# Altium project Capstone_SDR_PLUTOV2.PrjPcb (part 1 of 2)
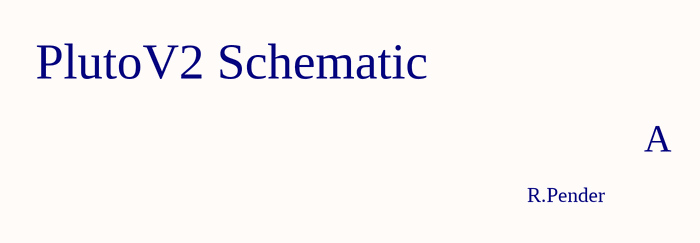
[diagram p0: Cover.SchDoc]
13 sheets, 418 parts. Net scope: global (net labels, ports and power ports of the same name join across sheets).
Sheets:
  Cover.SchDoc
  USB.SchDoc
  DDR3.SchDoc
  ZYNQ JTAG and Decoupling.SchDoc
  ZYNQ 34_35 and QPSI.SchDoc
  AD9363.SchDoc
  RF FRONTEND.SchDoc
  CONNECTORS_SELECTORS.SchDoc
  POWERREG.SchDoc
  POWERMANAGE.SchDoc
  POWERMANAGE2.SchDoc
  TESTPOINTS.SchDoc
  AD9363 OSCILLATORS.SchDoc

## Sheet Cover.SchDoc
size A3; SheetNumber: 1; SheetTotal: 2

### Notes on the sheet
- PlutoV2 Schematic
- A
- R.Pender

## Sheet USB.SchDoc
size A3; SheetNumber: 2; SheetTotal: 13; SPICEModelCacheQEWUXKYK: <root> / <DocumentId>QEWUXKYK</DocumentId> / </root>
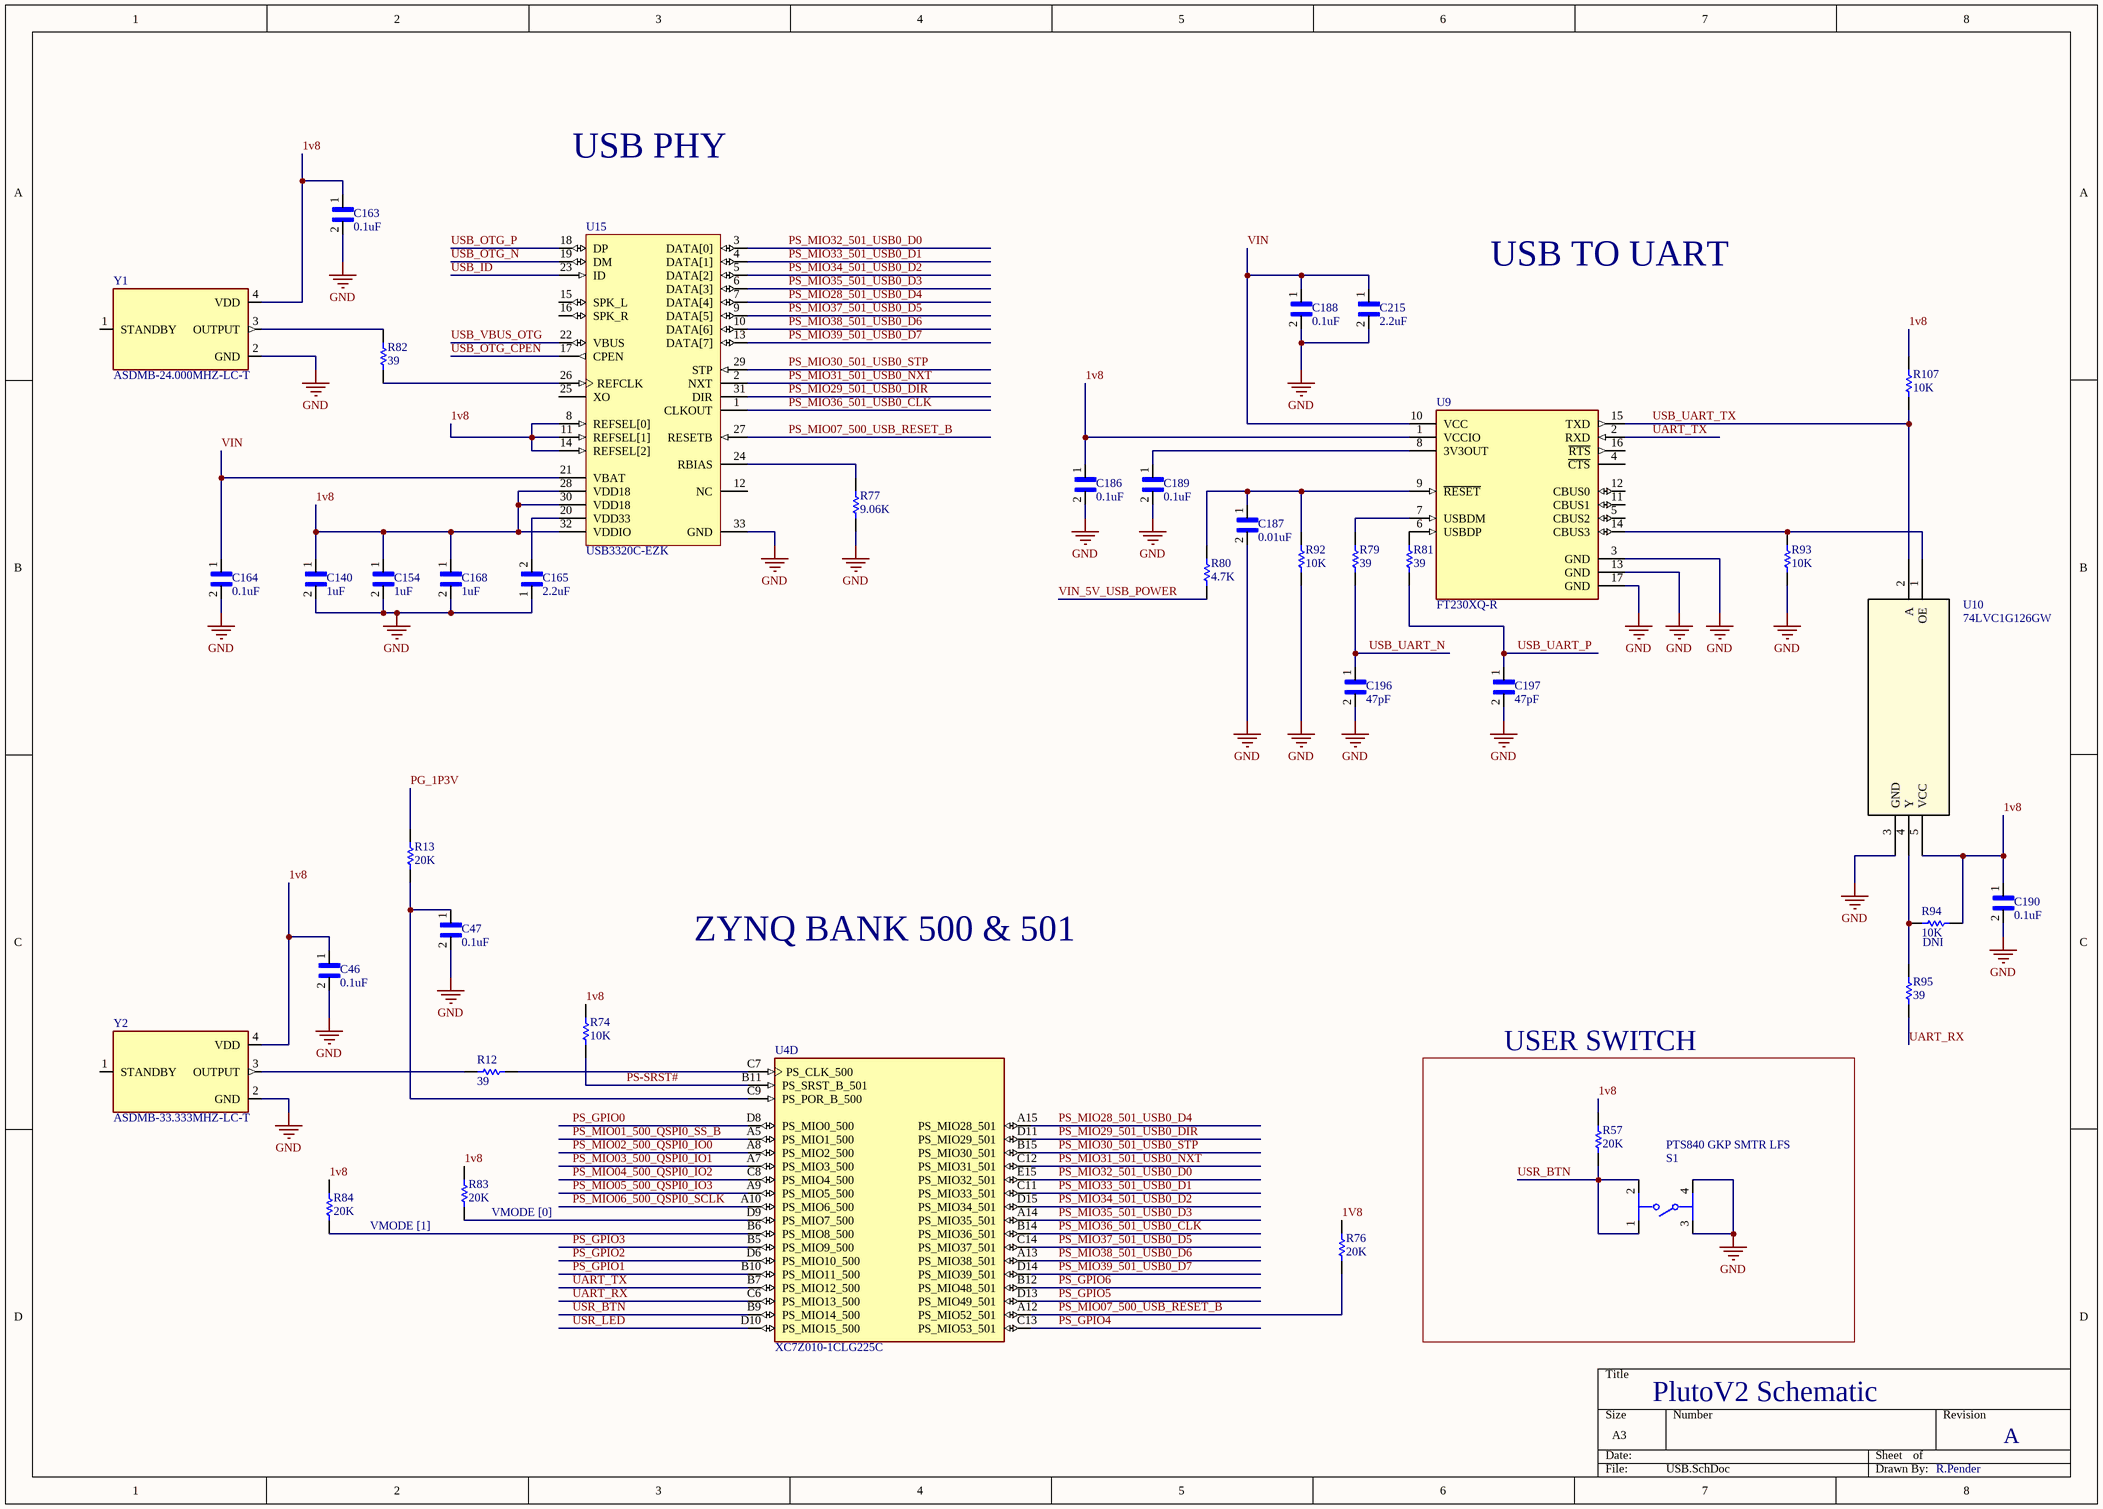
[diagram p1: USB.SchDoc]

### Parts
C46  0.1uF  [CAPC0603X33N]
C47  0.1uF  [CAPC0603X33N]
C140  1uF  [CAPC1005X55N]
C154  1uF  [CAPC1005X55N]
C163  0.1uF  [CAPC0603X33N]
C164  0.1uF  [CAPC0603X33N]
C165  2.2uF  [CAPC1608X100N]
C168  1uF  [CAPC1005X55N]
C186  0.1uF  [CAPC1005X55N]
C187  0.01uF  [CAPC0603X33N]
C188  0.1uF  [CAPC0603X33N]
C189  0.1uF  [CAPC0603X33N]
C190  0.1uF  [CAPC0603X33N]
C196  47pF  [CAPC1005X55N]
C197  47pF  [CAPC1005X55N]
C215  2.2uF  [CAPC1608X100N]
R12  39  [2-0402]
R13  20K  [2-0402]
R57  20K  [2-0402]
R74  10K  [2-0402]
R76  20K  [2-0402]
R77  9.06K  [2-0402]
R79  39  [2-0402]
R80  4.7K  [2-0402]
R81  39  [2-0402]
R82  39  [2-0402]
R83  20K  [2-0402]
R84  20K  [2-0402]
R92  10K  [2-0402]
R93  10K  [2-0402]
R94  10K  [2-0402]
R95  39  [2-0402]
R107  10K  [2-0402]
S1  PTS840 GKP SMTR LFS  [FP-PTS840_GKP_SMTR_LFS-MFG]
U4  XC7Z010-1CLG225C  [BGA225C80P15X15_1300X1300X150]  (part D of 6)
U9  FT230XQ-R  [FP-QFN-16-MFG]
U10  74LVC1G126GW  [SOT353-1_NXP]
U15  USB3320C-EZK  [MCHP-QFN-32-5x5_V2]
Y1  ASDMB-24.000MHZ-LC-T  [XTAL_ASDMB-24.000MHZ-LC-T]
Y2  ASDMB-33.333MHZ-LC-T  [XTAL_ASDMB-24.000MHZ-LC-T]

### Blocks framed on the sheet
USER SWITCH: R57 S1

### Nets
GND: C46.2 C47.2 C140.2 C154.2 C163.2 C164.2 C165.1 C168.2 C186.2 C187.2 C188.2 C189.2 C190.2 C196.2 C197.2 C215.2 R77.1 R92.1 R93.2 S1.3 S1.4 U9.3(GND) U9.13(GND) U9.17(GND) U10.3(GND) U15.33(GND) Y1.2(GND) Y2.2(GND)
1v8: C46.1 C140.1 C154.1 C163.1 C168.1 C186.1 C190.1 R57.1 R74.2 R76.2 R83.1 R84.1 R94.2 R107.1 U9.1(VCCIO) U10.5(VCC) U15.8(REFSEL[0]) U15.11(REFSEL[1]) U15.14(REFSEL[2]) U15.28(VDD18) U15.30(VDD18) U15.32(VDDIO) Y1.4(VDD) Y2.4(VDD)
PG_1P3V: R13.2
PS-SRST#: R74.1 U4.B11(PS_SRST_B_501)
PS_GPIO0: U4.D8(PS_MIO0_500)
PS_GPIO1: U4.B10(PS_MIO11_500)
PS_GPIO2: U4.D6(PS_MIO10_500)
PS_GPIO3: U4.B5(PS_MIO9_500)
PS_GPIO4: U4.C13(PS_MIO53_501)
PS_GPIO5: U4.D13(PS_MIO49_501)
PS_GPIO6: U4.B12(PS_MIO48_501)
PS_MIO01_500_QSPI0_SS_B: U4.A5(PS_MIO1_500)
PS_MIO02_500_QSPI0_IO0: U4.A8(PS_MIO2_500)
PS_MIO03_500_QSPI0_IO1: U4.A7(PS_MIO3_500)
PS_MIO04_500_QSPI0_IO2: U4.C8(PS_MIO4_500)
PS_MIO05_500_QSPI0_IO3: U4.A9(PS_MIO5_500)
PS_MIO06_500_QSPI0_SCLK: U4.A10(PS_MIO6_500)
PS_MIO07_500_USB_RESET_B: R76.1 U4.A12(PS_MIO52_501) U15.27(RESETB)
PS_MIO28_501_USB0_D4: U4.A15(PS_MIO28_501) U15.7(DATA[4])
PS_MIO29_501_USB0_DIR: U4.D11(PS_MIO29_501) U15.31(DIR)
PS_MIO30_501_USB0_STP: U4.B15(PS_MIO30_501) U15.29(STP)
PS_MIO31_501_USB0_NXT: U4.C12(PS_MIO31_501) U15.2(NXT)
PS_MIO32_501_USB0_D0: U4.E15(PS_MIO32_501) U15.3(DATA[0])
PS_MIO33_501_USB0_D1: U4.C11(PS_MIO33_501) U15.4(DATA[1])
PS_MIO34_501_USB0_D2: U4.D15(PS_MIO34_501) U15.5(DATA[2])
PS_MIO35_501_USB0_D3: U4.A14(PS_MIO35_501) U15.6(DATA[3])
PS_MIO36_501_USB0_CLK: U4.B14(PS_MIO36_501) U15.1(CLKOUT)
PS_MIO37_501_USB0_D5: U4.C14(PS_MIO37_501) U15.9(DATA[5])
PS_MIO38_501_USB0_D6: U4.A13(PS_MIO38_501) U15.10(DATA[6])
PS_MIO39_501_USB0_D7: U4.D14(PS_MIO39_501) U15.13(DATA[7])
UART_RX: R95.2 U4.C6(PS_MIO13_500)
UART_TX: U4.B7(PS_MIO12_500) U9.2(RXD)
USB_ID: U15.23(ID)
USB_OTG_CPEN: U15.17(CPEN)
USB_OTG_N: U15.19(DM)
USB_OTG_P: U15.18(DP)
USB_UART_N: C196.1 R79.2
USB_UART_P: C197.1 R81.1
USB_UART_TX: R107.2 U9.15(TXD) U10.2(A)
USB_VBUS_OTG: U15.22(VBUS)
USR_BTN: R57.2 S1.1 S1.2 U4.B9(PS_MIO14_500)
USR_LED: U4.D10(PS_MIO15_500)
VIN: C164.1 C188.1 C215.1 U9.10(VCC) U15.21(VBAT)
VIN_5V_USB_POWER: R80.1
NetC47_1: C47.1 R13.1 U4.C9(PS_POR_B_500)
NetC165_2: C165.2 U15.20(VDD33)
NetC187_1: C187.1 R80.2 R92.2 U9.9(~{RESET})
NetC189_1: C189.1 U9.8(3V3OUT)
NetR12_1: R12.1 Y2.3(OUTPUT)
NetR12_2: R12.2 U4.C7(PS_CLK_500)
NetR77_2: R77.2 U15.24(RBIAS)
NetR79_1: R79.1 U9.7(USBDM)
NetR81_2: R81.2 U9.6(USBDP)
NetR82_1: R82.1 U15.26(REFCLK)
NetR82_2: R82.2 Y1.3(OUTPUT)
NetR83_2: R83.2 U4.D9(PS_MIO7_500)
NetR84_2: R84.2 U4.B6(PS_MIO8_500)
NetR93_1: R93.1 U9.14(CBUS3) U10.1(OE)
NetR94_1: R94.1 R95.1 U10.4(Y)

Not connected (* = marked no-connect by the designer): U9 4(~{CTS}) 5(CBUS2) 11(CBUS1) 12(CBUS0) 16(~{RTS}); U15 12(NC) 15(SPK_L) 16(SPK_R) 25(XO); Y1 1(STANDBY); Y2 1(STANDBY)

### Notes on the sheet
- USB PHY
- USB TO UART
- ZYNQ BANK 500 & 501
- (near R94) DNI
- VMODE [1]
- (near R83) VMODE [0]
- PlutoV2 Schematic
- A
- R.Pender

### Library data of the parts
C46 C47 C163 C164 C188-C190 = GRM033R61C104ME84D: CAP 0.1UF 16VDC X5R 20% SMD 0201 PAPER TAPE
C140 C154 C168 C186 = EMK105BJ105KV-F: 1ÂµF Â± 10% 16V Condensateur cÃ©ramique X5R 0402 _1005 mÃ©trique_; MF: Taiyo Yuden
C165 C215 = GRM188R61H225KE11J: SMD Capacitor X5R(EIA) with Capacitance: 2.2uF Tol. 10%. Rated Voltage: 50Vdc; MF: Murata
C187 = GRM033R71A103KA01D: SMD Capacitor X7R(EIA) with Capacitance: 10000pF Tol. 10%. Rated Voltage: 10Vdc; MF: Murata
C196 C197 = GCM1555C1H470JA16D: 47pF Â±5% 50V Ceramic Capacitor C0G, NP0 0402 (1005 Metric); MF: Murata
R12 R79 R81 R82 R95 = ERJ2GE: Thick Film Chip Resistor, 1 Ohm to 2.2M Ohm Range, 5% Tolerance, 0402 Size, 0.063 W; Note: If flow soldering, adjust pad width of PCB Footprint to 0.7 - 0.8 times the width of the resistor.
R13 R57 R74 R76 R77 R80 R83 R84 R92-R94 R107 = ERJ2RK: Precision Thick Film Chip Resistor, 10 Ohm to 1M Ohm Range, 1% and 0.5% Tolerance, 0402 Size, 0.063 W
S1 = CMP-10040-000012-1: SWITCH TACTILE SPST-NO 0.05A 12V; Manufacturer: C&K Components; Electromechanical Life: 100000Cycles; Contact Current Rating: 50mA; Operating Force: 220gf; Standoff Height: 0mm; Contact Resistance: 500mΩ
U4 = XC7Z010-1CLG225C: Dual ARMÂ® CortexÂ®-A9 MPCoreâ„¢ with CoreSightâ„¢ System On Chip _SOC_ IC ZynqÂ®-7000 Artixâ„¢-7 FPGA, 28K Logic Cells 667MHz 225-CSPBGA _13x13_; MF: Xilinx Inc.
U9 = CMP-0248-00010-3: IC USB SERIAL BASIC UART 16QFN; Number of Channels: 1; Data Rate: 12Mbps; Operating Supply Current: 8mA; Max Supply Voltage: 5.5V; Operating Supply Voltage: 5V; Min Supply Voltage: 2.97V
U10 = 74LVC1G126GW: No Description Available; Mfr_Name: NXP
U15 = CMP-0186-00335-1: Highly Integrated Full Featured Hi-Speed USB 2.0 ULPI Transceiver, 1.8 to 3.3 V, -40 to 85 degC, 32-Pin QFN (QFN-3304), RoHS, Tray; Manufacturer: Microchip; VVBAT: 3.1 to 5.5 V; REFCLK Frequency@ULPI Input Clock Mode: 60 MHz; Cpin: 4 pF Max.; VDD33: 3 to 3.6 V
Y1 Y2 = ASDMB-24.000MHZ-LC-T: 24MHz XO _Standard_ LVCMOS Oscillator 1.8V ~ 3.3V Standby _Power Down_ 4-SMD, No Lead; MF: Abracon LLC

## Sheet DDR3.SchDoc
size A3; SheetNumber: 3; SheetTotal: 13; SPICEModelCacheAHASEUHE: <root> / <DocumentId>AHASEUHE</DocumentId> / </root>
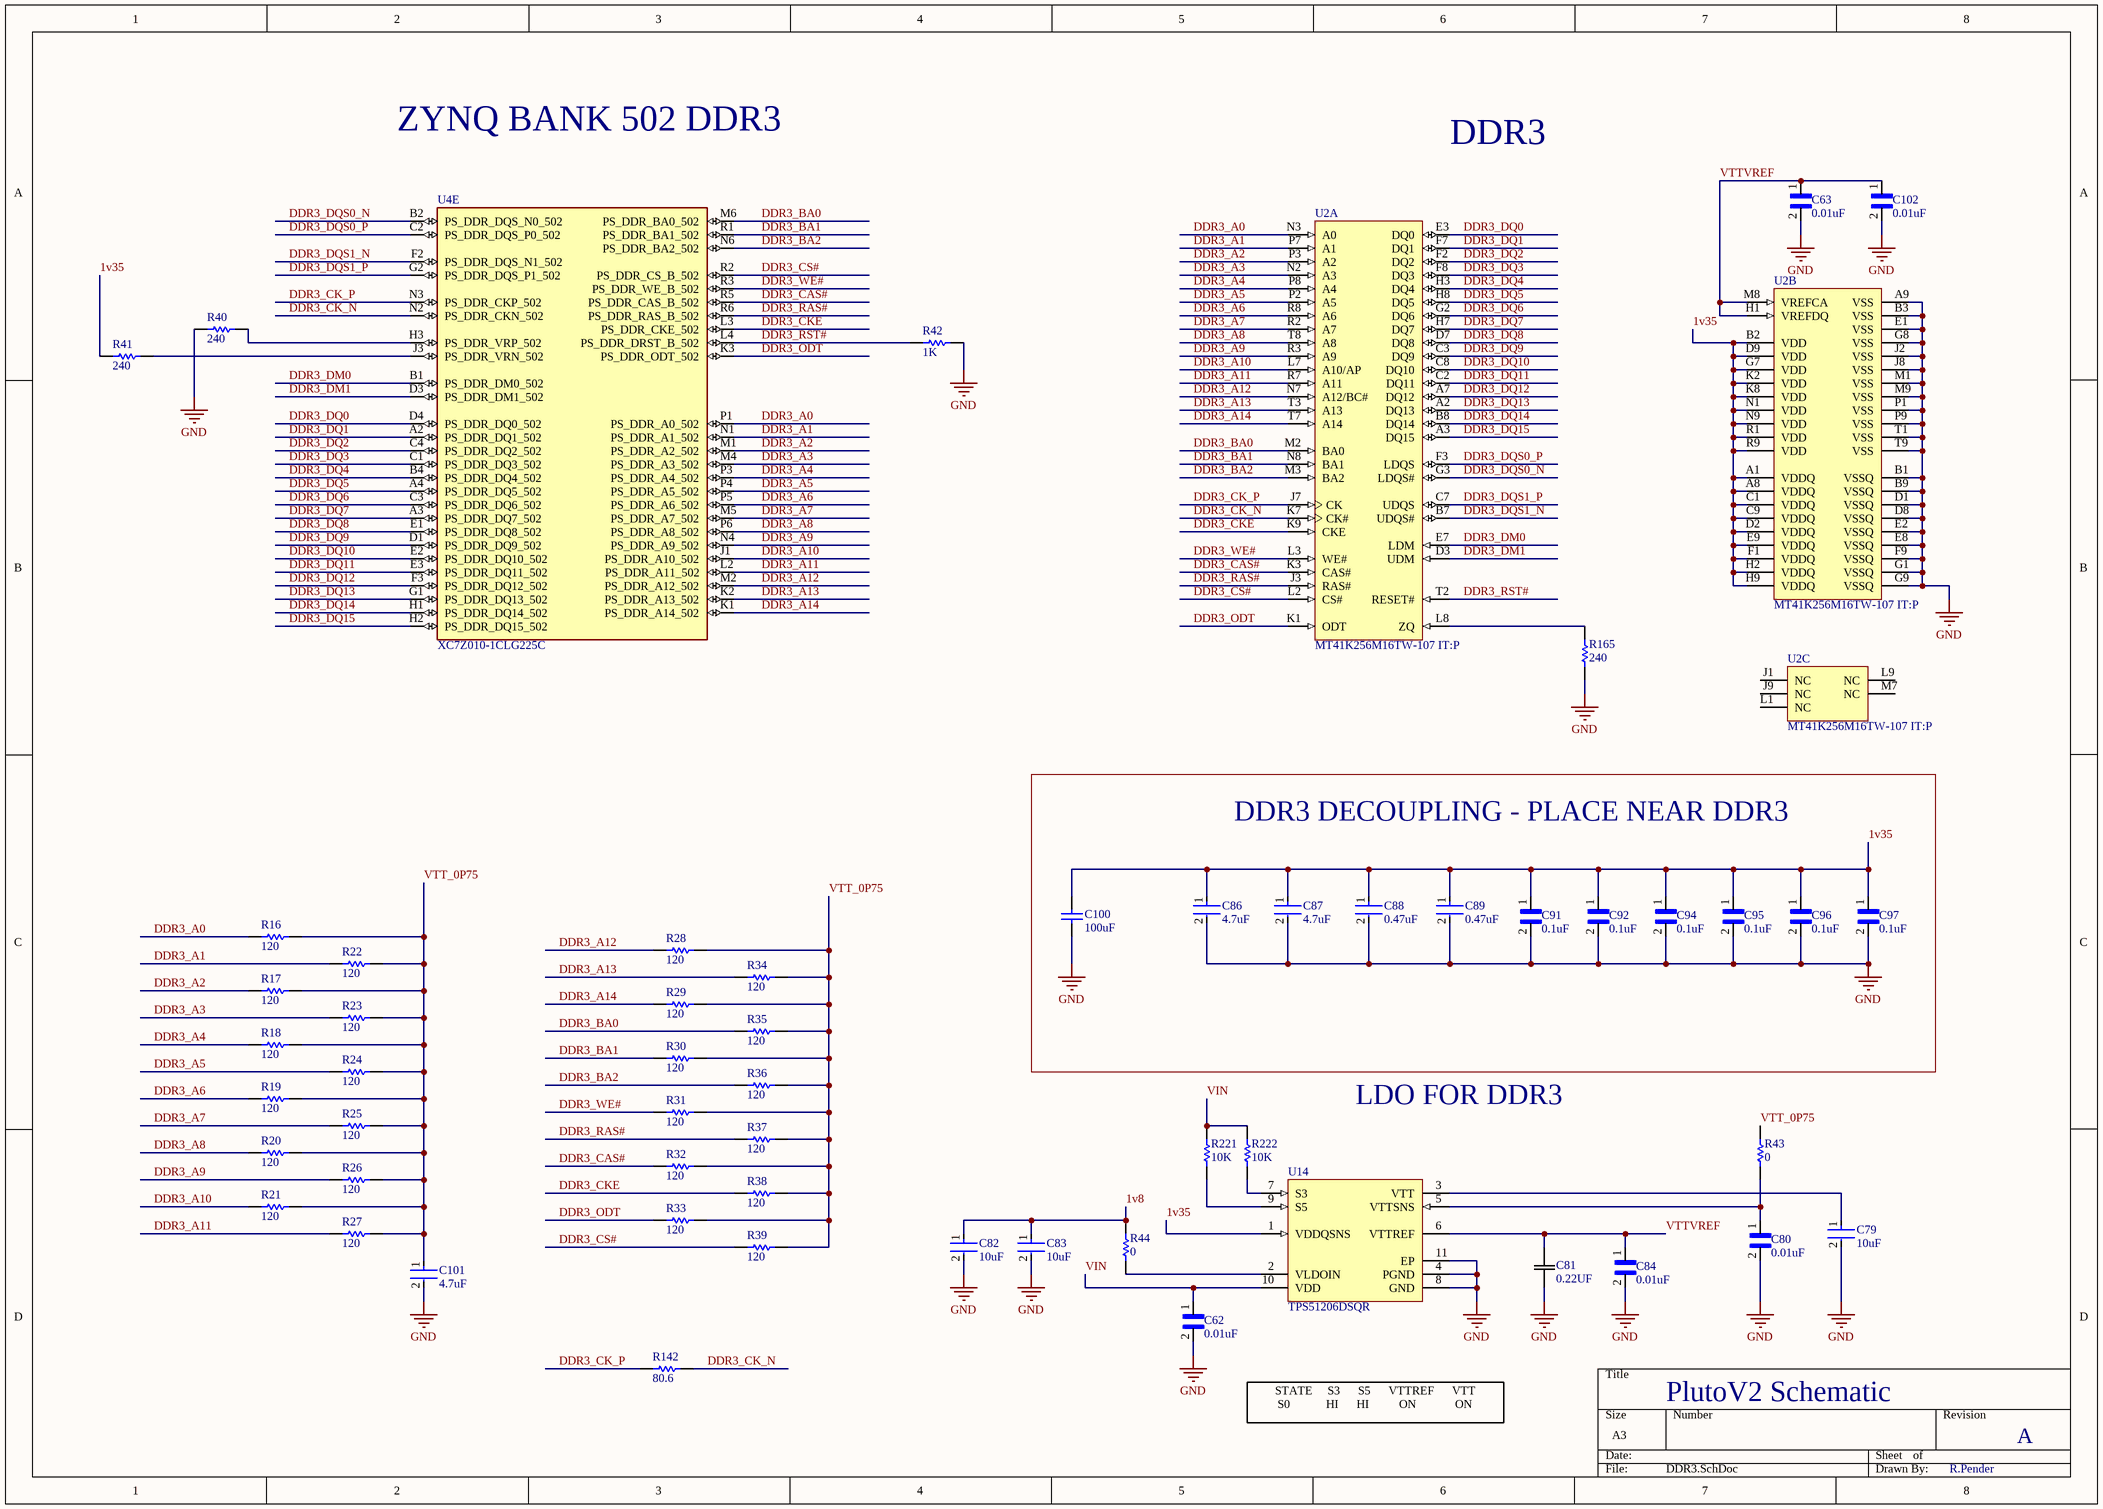
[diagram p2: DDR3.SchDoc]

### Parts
C62  0.01uF  [CAPC0603X33N]
C63  0.01uF  [CAPC0603X33N]
C79  10uF  [FP-GRM188-0_1-e0_2_0_55-IPC_A]
C80  0.01uF  [CAPC0603X33N]
C81  0.22UF  [CAP_U_0805_KNO]
C82  10uF  [FP-GRM188-0_1-e0_2_0_55-IPC_A]
C83  10uF  [FP-GRM188-0_1-e0_2_0_55-IPC_A]
C84  0.01uF  [CAPC0603X33N]
C86  4.7uF  [FP-C1005-050-0_15-MFG]
C87  4.7uF  [FP-C1005-050-0_15-MFG]
C88  0.47uF  [FP-C1005-050-0_15-MFG]
C89  0.47uF  [FP-C1005-050-0_15-MFG]
C91  0.1uF  [CAPC0603X33N]
C92  0.1uF  [CAPC0603X33N]
C94  0.1uF  [CAPC0603X33N]
C95  0.1uF  [CAPC0603X33N]
C96  0.1uF  [CAPC0603X33N]
C97  0.1uF  [CAPC0603X33N]
C100  100uF  [CAPC3216X190X55ML30T25]
C101  4.7uF  [FP-C1005-050-0_15-MFG]
C102  0.01uF  [CAPC0603X33N]
R16  120  [1-0201]
R17  120  [1-0201]
R18  120  [1-0201]
R19  120  [1-0201]
R20  120  [1-0201]
R21  120  [1-0201]
R22  120  [1-0201]
R23  120  [1-0201]
R24  120  [1-0201]
R25  120  [1-0201]
R26  120  [1-0201]
R27  120  [1-0201]
R28  120  [1-0201]
R29  120  [1-0201]
R30  120  [1-0201]
R31  120  [1-0201]
R32  120  [1-0201]
R33  120  [1-0201]
R34  120  [1-0201]
R35  120  [1-0201]
R36  120  [1-0201]
R37  120  [1-0201]
R38  120  [1-0201]
R39  120  [1-0201]
R40  240  [2-0402]
R41  240  [2-0402]
R42  1K  [2-0402]
R43  0  [RESC1005X40X25NL10T10]
R44  0  [RESC1005X40X25NL10T10]
R142  80.6  [2-0402]
R165  240  [2-0402]
R221  10K  [2-0402]
R222  10K  [2-0402]
U2  MT41K256M16TW-107 IT:P  [MICT-TW-96]  (parts A,B,C of 3)
U4  XC7Z010-1CLG225C  [BGA225C80P15X15_1300X1300X150]  (part E of 6)
U14  TPS51206DSQR  [DSQ0010A_V]

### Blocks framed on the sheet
DDR3 DECOUPLING - PLACE NEAR DDR3: C86-C89 C91 C92 C94-C97 C100

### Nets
GND: C62.2 C63.2 C79.2 C80.2 C81.2 C82.2 C83.2 C84.2 C86.2 C87.2 C88.2 C89.2 C91.2 C92.2 C94.2 C95.2 C96.2 C97.2 C100.2 C101.2 C102.2 R40.1 R42.2 R165.2 U2.A9(VSS) U2.B1(VSSQ) U2.B3(VSS) U2.B9(VSSQ) U2.D1(VSSQ) U2.D8(VSSQ) U2.E1(VSS) U2.E2(VSSQ) U2.E8(VSSQ) U2.F9(VSSQ) U2.G1(VSSQ) U2.G8(VSS) U2.G9(VSSQ) U2.J2(VSS) U2.J8(VSS) U2.M1(VSS) U2.M9(VSS) U2.P1(VSS) U2.P9(VSS) U2.T1(VSS) U2.T9(VSS) U14.4(PGND) U14.8(GND) U14.11(EP)
1v8: C82.1 C83.1 R44.1
1v35: C86.1 C87.1 C88.1 C89.1 C91.1 C92.1 C94.1 C95.1 C96.1 C97.1 C100.1 R41.1 U2.A1(VDDQ) U2.A8(VDDQ) U2.B2(VDD) U2.C1(VDDQ) U2.C9(VDDQ) U2.D2(VDDQ) U2.D9(VDD) U2.E9(VDDQ) U2.F1(VDDQ) U2.G7(VDD) U2.H2(VDDQ) U2.H9(VDDQ) U2.K2(VDD) U2.K8(VDD) U2.N1(VDD) U2.N9(VDD) U2.R1(VDD) U2.R9(VDD) U14.1(VDDQSNS)
DDR3_A0: R16.1 U2.N3(A0) U4.P1(PS_DDR_A0_502)
DDR3_A1: R22.1 U2.P7(A1) U4.N1(PS_DDR_A1_502)
DDR3_A2: R17.1 U2.P3(A2) U4.M1(PS_DDR_A2_502)
DDR3_A3: R23.1 U2.N2(A3) U4.M4(PS_DDR_A3_502)
DDR3_A4: R18.1 U2.P8(A4) U4.P3(PS_DDR_A4_502)
DDR3_A5: R24.1 U2.P2(A5) U4.P4(PS_DDR_A5_502)
DDR3_A6: R19.1 U2.R8(A6) U4.P5(PS_DDR_A6_502)
DDR3_A7: R25.1 U2.R2(A7) U4.M5(PS_DDR_A7_502)
DDR3_A8: R20.1 U2.T8(A8) U4.P6(PS_DDR_A8_502)
DDR3_A9: R26.1 U2.R3(A9) U4.N4(PS_DDR_A9_502)
DDR3_A10: R21.1 U2.L7(A10/AP) U4.J1(PS_DDR_A10_502)
DDR3_A11: R27.1 U2.R7(A11) U4.L2(PS_DDR_A11_502)
DDR3_A12: R28.1 U2.N7(A12/BC#) U4.M2(PS_DDR_A12_502)
DDR3_A13: R34.1 U2.T3(A13) U4.K2(PS_DDR_A13_502)
DDR3_A14: R29.1 U2.T7(A14) U4.K1(PS_DDR_A14_502)
DDR3_BA0: R35.1 U2.M2(BA0) U4.M6(PS_DDR_BA0_502)
DDR3_BA1: R30.1 U2.N8(BA1) U4.R1(PS_DDR_BA1_502)
DDR3_BA2: R36.1 U2.M3(BA2) U4.N6(PS_DDR_BA2_502)
DDR3_CAS#: R32.1 U2.K3(CAS#) U4.R5(PS_DDR_CAS_B_502)
DDR3_CK_N: R142.2 U2.K7(CK#) U4.N2(PS_DDR_CKN_502)
DDR3_CK_P: R142.1 U2.J7(CK) U4.N3(PS_DDR_CKP_502)
DDR3_CKE: R38.1 U2.K9(CKE) U4.L3(PS_DDR_CKE_502)
DDR3_CS#: R39.1 U2.L2(CS#) U4.R2(PS_DDR_CS_B_502)
DDR3_DM0: U2.E7(LDM) U4.B1(PS_DDR_DM0_502)
DDR3_DM1: U2.D3(UDM) U4.D3(PS_DDR_DM1_502)
DDR3_DQ0: U2.E3(DQ0) U4.D4(PS_DDR_DQ0_502)
DDR3_DQ1: U2.F7(DQ1) U4.A2(PS_DDR_DQ1_502)
DDR3_DQ2: U2.F2(DQ2) U4.C4(PS_DDR_DQ2_502)
DDR3_DQ3: U2.F8(DQ3) U4.C1(PS_DDR_DQ3_502)
DDR3_DQ4: U2.H3(DQ4) U4.B4(PS_DDR_DQ4_502)
DDR3_DQ5: U2.H8(DQ5) U4.A4(PS_DDR_DQ5_502)
DDR3_DQ6: U2.G2(DQ6) U4.C3(PS_DDR_DQ6_502)
DDR3_DQ7: U2.H7(DQ7) U4.A3(PS_DDR_DQ7_502)
DDR3_DQ8: U2.D7(DQ8) U4.E1(PS_DDR_DQ8_502)
DDR3_DQ9: U2.C3(DQ9) U4.D1(PS_DDR_DQ9_502)
DDR3_DQ10: U2.C8(DQ10) U4.E2(PS_DDR_DQ10_502)
DDR3_DQ11: U2.C2(DQ11) U4.E3(PS_DDR_DQ11_502)
DDR3_DQ12: U2.A7(DQ12) U4.F3(PS_DDR_DQ12_502)
DDR3_DQ13: U2.A2(DQ13) U4.G1(PS_DDR_DQ13_502)
DDR3_DQ14: U2.B8(DQ14) U4.H1(PS_DDR_DQ14_502)
DDR3_DQ15: U2.A3(DQ15) U4.H2(PS_DDR_DQ15_502)
DDR3_DQS0_N: U2.G3(LDQS#) U4.B2(PS_DDR_DQS_N0_502)
DDR3_DQS0_P: U2.F3(LDQS) U4.C2(PS_DDR_DQS_P0_502)
DDR3_DQS1_N: U2.B7(UDQS#) U4.F2(PS_DDR_DQS_N1_502)
DDR3_DQS1_P: U2.C7(UDQS) U4.G2(PS_DDR_DQS_P1_502)
DDR3_ODT: R33.1 U2.K1(ODT) U4.K3(PS_DDR_ODT_502)
DDR3_RAS#: R37.1 U2.J3(RAS#) U4.R6(PS_DDR_RAS_B_502)
DDR3_RST#: R42.1 U2.T2(RESET#) U4.L4(PS_DDR_DRST_B_502)
DDR3_WE#: R31.1 U2.L3(WE#) U4.R3(PS_DDR_WE_B_502)
VIN: C62.1 R221.1 R222.1 U14.10(VDD)
VTT_0P75: C101.1 R16.2 R17.2 R18.2 R19.2 R20.2 R21.2 R22.2 R23.2 R24.2 R25.2 R26.2 R27.2 R28.2 R29.2 R30.2 R31.2 R32.2 R33.2 R34.2 R35.2 R36.2 R37.2 R38.2 R39.2 R43.1
VTTVREF: C63.1 C81.1 C84.1 C102.1 U2.H1(VREFDQ) U2.M8(VREFCA) U14.6(VTTREF)
NetC79_1: C79.1 U14.3(VTT)
NetC80_1: C80.1 R43.2 U14.5(VTTSNS)
NetR40_2: R40.2 U4.H3(PS_DDR_VRP_502)
NetR41_2: R41.2 U4.J3(PS_DDR_VRN_502)
NetR44_2: R44.2 U14.2(VLDOIN)
NetR165_1: R165.1 U2.L8(ZQ)
NetR221_2: R221.2 U14.9(S5)
NetR222_2: R222.2 U14.7(S3)

Not connected (* = marked no-connect by the designer): U2 J1(NC) J9(NC) L1(NC) L9(NC) M7(NC)

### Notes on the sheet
- ZYNQ BANK 502 DDR3
- DDR3
- LDO FOR DDR3
- STATE     S3      S5      VTTREF      VTT                                       S0            HI      HI          ON             ON
- PlutoV2 Schematic
- A
- R.Pender

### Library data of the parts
C62 C63 C80 C84 C102 = GRM033R71A103KA01D: as C187 on sheet USB
C79 C82 C83 = CMP-2006-02792-2: Chip Multilayer Ceramic Capacitors for General Purpose, 0603, 10uF, X5R, 15%, 20%, 6.3V
C81 = 080530250224KXT: No Description Available; Mfr_Name: Knowles; Type: DEV
C86-C89 C101 = CMP-2000-05437-2: CAP CER 4.7UF 6.3V X5R 0402; Tolerance: 10%; Dielectric Material: Ceramic
C91 C92 C94-C97 = GRM033R61C104ME84D: as C46 on sheet USB
C100 = CMP-1662-00011-2: Chip Capacitor, 100 uF, +/- 20%, 6.3 V, -55 to 85 degC, 1206 (3216 Metric), RoHS, Tape and Reel; PartNumber: GRM31CR60J107ME39L; Case\/Package: 1206; Voltage Rating (DC): 6.3 V; Type (Capacitors): X5R
R16-R39 = ERJ1GE: Thick Film Chip Resistor, 10 Ohm to 1M Ohm Range, 5% Tolerance, 0201 Size, 0.05 W; Note: If flow soldering, adjust pad width of PCB Footprint to 0.7 - 0.8 times the width of the resistor.
R40-R42 R142 R165 R221 R222 = ERJ2RK: as R13 on sheet USB
R43 R44 = CMP-2002-05896-1: Part Number: MC00625W040210R; Manufacturer: Multicomp
U2 = CMP-2000-06773-2: Automotive DDR3L SDRAM, 4 GB, 933 MHz, 1.283 to 1.45 V, -40 to 95 degC, 96-Pin TFBGA, RoHS, Tray; Manufacturer: Micron; Data Bus Width: 16b; Address Bus Width: 15b; Operating Supply Voltage: 1.35V; Access Time: 1.07ns; Max Frequency: 933MHz; Density: 4Gb
U4 = XC7Z010-1CLG225C: as U4 on sheet USB
U14 = CMP-0395-00678-2: Single Output LDO, 2 A, with VTTREF Buffered Reference for DDR2, DDR3, DDR3L, 10-pin SON (DSQ), -40 to 85 degC, Green (RoHS & no Sb/Br); Manufacturer: Texas Instruments; SubFamily: Single Channel LDO; Iout(Max)(A): 2; Rating: Catalog

## Sheet ZYNQ JTAG and Decoupling.SchDoc
size A3; SheetNumber: 4; SheetTotal: 13; SPICEModelCacheIAXUMUHC: <root> / <DocumentId>IAXUMUHC</DocumentId> / <CacheFrame Number="0"> / <Model Name="led3" Kind="MDL"> / <Text>*Typ BLUE SiC LED: Vf=3.4V Vr=5V If=40mA trr=3uS / *LED Pinout: 1=A, 2=K / .MODEL LED3 D (IS=93.1P RS=42M N=7.47 BV=5 IBV=30U / + CJO=2.97P VJ=.75 M=.333 TT=4.32U)</Text> / </Model> / </CacheFrame> / </root>
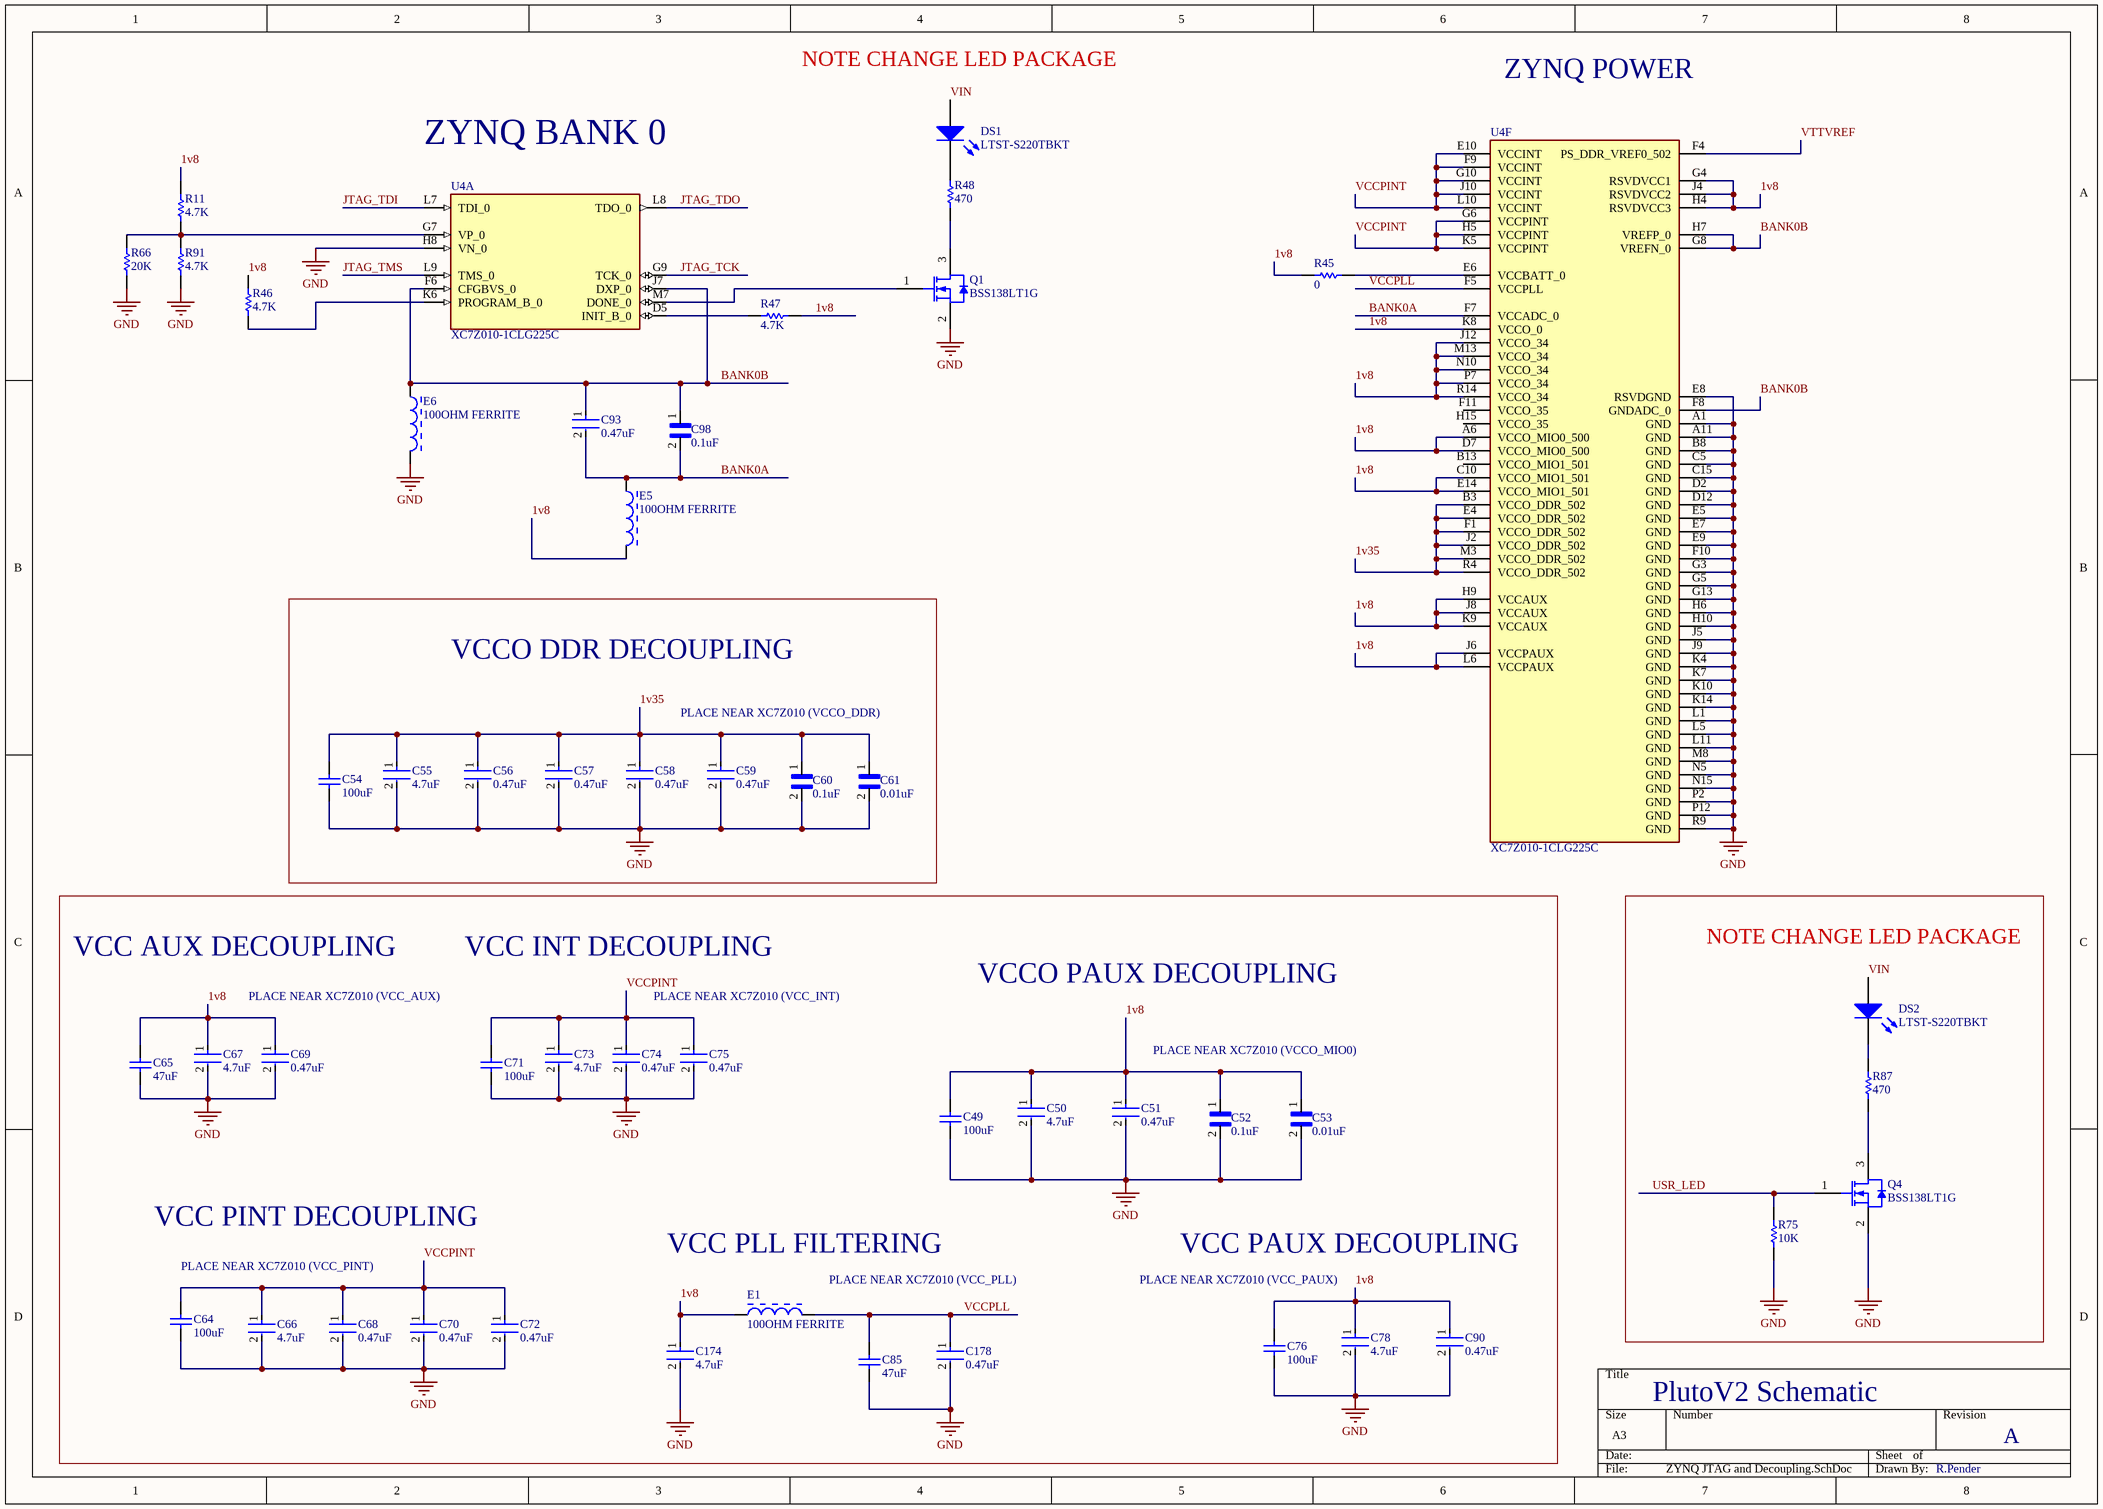
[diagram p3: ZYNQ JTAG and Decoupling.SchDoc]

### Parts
C49  100uF  [CAPC3216X190X55ML30T25]
C50  4.7uF  [FP-C1005-050-0_15-MFG]
C51  0.47uF  [FP-C1005-050-0_15-MFG]
C52  0.1uF  [CAPC0603X33N]
C53  0.01uF  [CAPC0603X33N]
C54  100uF  [CAPC3216X190X55ML30T25]
C55  4.7uF  [FP-C1005-050-0_15-MFG]
C56  0.47uF  [FP-C1005-050-0_15-MFG]
C57  0.47uF  [FP-C1005-050-0_15-MFG]
C58  0.47uF  [FP-C1005-050-0_15-MFG]
C59  0.47uF  [FP-C1005-050-0_15-MFG]
C60  0.1uF  [CAPC0603X33N]
C61  0.01uF  [CAPC0603X33N]
C64  100uF  [CAPC3216X190X55LL30T25]
C65  47uF  [TAYO-JMK212BBJ476MG-T_L]
C66  4.7uF  [FP-C1005-050-0_15-MFG]
C67  4.7uF  [FP-C1005-050-0_15-MFG]
C68  0.47uF  [FP-C1005-050-0_15-MFG]
C69  0.47uF  [FP-C1005-050-0_15-MFG]
C70  0.47uF  [FP-C1005-050-0_15-MFG]
C71  100uF  [CAPC3216X190X55LL30T25]
C72  0.47uF  [FP-C1005-050-0_15-MFG]
C73  4.7uF  [FP-C1005-050-0_15-MFG]
C74  0.47uF  [FP-C1005-050-0_15-MFG]
C75  0.47uF  [FP-C1005-050-0_15-MFG]
C76  100uF  [CAPC3216X190X55LL30T25]
C78  4.7uF  [FP-C1005-050-0_15-MFG]
C85  47uF  [TAYO-JMK212BBJ476MG-T_L]
C90  0.47uF  [FP-C1005-050-0_15-MFG]
C93  0.47uF  [FP-C1005-050-0_15-MFG]
C98  0.1uF  [CAPC0603X33N]
C174  4.7uF  [FP-C1005-050-0_15-MFG]
C178  0.47uF  [FP-C1005-050-0_15-MFG]
DS1  LTST-S220TBKT  [3.5X2.8X1.9]
DS2  LTST-S220TBKT  [3.5X2.8X1.9]
E1  100OHM FERRITE  [TDK-MPZ2012S101A-2_V]
E5  100OHM FERRITE  [TDK-MPZ2012S101A-2_V]
E6  100OHM FERRITE  [TDK-MPZ2012S101A-2_V]
Q1  BSS138LT1G  [ONSC-SOT-23-3-318-08_V]
Q4  BSS138LT1G  [ONSC-SOT-23-3-318-08_V]
R11  4.7K  [2-0402]
R45  0  [RESC1005X40X25ML10T10]
R46  4.7K  [2-0402]
R47  4.7K  [2-0402]
R48  470  [2-0402]
R66  20K  [2-0402]
R75  10K  [2-0402]
R87  470  [2-0402]
R91  4.7K  [2-0402]
U4  XC7Z010-1CLG225C  [BGA225C80P15X15_1300X1300X150]  (parts A,F of 6)

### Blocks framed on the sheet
VCCO DDR DECOUPLING: C54-C61
NOTE CHANGE LED PACKAGE: DS2 Q4 R75 R87

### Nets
GND: C49.2 C50.2 C51.2 C52.2 C53.2 C54.1 C55.2 C56.2 C57.2 C58.2 C59.2 C60.2 C61.2 C64.1 C65.2 C66.2 C67.2 C68.2 C69.2 C70.2 C71.1 C72.2 C73.2 C74.2 C75.2 C76.2 C78.2 C85.1 C90.2 C174.2 C178.2 E6.2 Q1.2(S) Q4.2(S) R66.2 R75.2 R91.2 U4.A1(GND) U4.A11(GND) U4.B8(GND) U4.C5(GND) U4.C15(GND) U4.D2(GND) U4.D12(GND) U4.E5(GND) U4.E7(GND) U4.E8(RSVDGND) U4.E9(GND) U4.F10(GND) U4.G3(GND) U4.G5(GND) U4.G13(GND) U4.H6(GND) U4.H8(VN_0) U4.H10(GND) U4.J5(GND) U4.J9(GND) U4.K4(GND) U4.K7(GND) U4.K10(GND) U4.K14(GND) U4.L1(GND) U4.L5(GND) U4.L11(GND) U4.M8(GND) U4.N5(GND) U4.N15(GND) U4.P2(GND) U4.P12(GND) U4.R9(GND)
1v8: C49.1 C50.1 C51.1 C52.1 C53.1 C65.1 C67.1 C69.1 C76.1 C78.1 C90.1 C174.1 E1.1 E5.2 R11.1 R45.1 R46.1 R47.1 U4.A6(VCCO_MIO0_500) U4.C10(VCCO_MIO1_501) U4.D7(VCCO_MIO0_500) U4.E14(VCCO_MIO1_501) U4.G4(RSVDVCC1) U4.H4(RSVDVCC3) U4.H9(VCCAUX) U4.J4(RSVDVCC2) U4.J6(VCCPAUX) U4.J8(VCCAUX) U4.J12(VCCO_34) U4.K8(VCCO_0) U4.K9(VCCAUX) U4.L6(VCCPAUX) U4.M13(VCCO_34) U4.N10(VCCO_34) U4.P7(VCCO_34) U4.R14(VCCO_34)
1v35: C54.2 C55.1 C56.1 C57.1 C58.1 C59.1 C60.1 C61.1 U4.B3(VCCO_DDR_502) U4.E4(VCCO_DDR_502) U4.F1(VCCO_DDR_502) U4.J2(VCCO_DDR_502) U4.M3(VCCO_DDR_502) U4.R4(VCCO_DDR_502)
BANK0A: C93.2 C98.2 E5.1 U4.F7(VCCADC_0)
BANK0B: C93.1 C98.1 E6.1 U4.F6(CFGBVS_0) U4.F8(GNDADC_0) U4.G8(VREFN_0) U4.H7(VREFP_0) U4.J7(DXP_0)
JTAG_TCK: U4.G9(TCK_0)
JTAG_TDI: U4.L7(TDI_0)
JTAG_TDO: U4.L8(TDO_0)
JTAG_TMS: U4.L9(TMS_0)
USR_LED: Q4.1(G) R75.1
VCCPINT: C64.2 C66.1 C68.1 C70.1 C71.2 C72.1 C73.1 C74.1 C75.1 U4.E10(VCCINT) U4.F9(VCCINT) U4.G6(VCCPINT) U4.G10(VCCINT) U4.H5(VCCPINT) U4.J10(VCCINT) U4.K5(VCCPINT) U4.L10(VCCINT)
VCCPLL: C85.2 C178.1 E1.2 U4.F5(VCCPLL)
VIN: DS1.1(A) DS2.1(A)
VTTVREF: U4.F4(PS_DDR_VREF0_502)
NetDS1_2: DS1.2(K) R48.1
NetDS2_2: DS2.2(K) R87.1
NetQ1_1: Q1.1(G) U4.M7(DONE_0)
NetQ1_3: Q1.3(D) R48.2
NetQ4_3: Q4.3(D) R87.2
NetR11_2: R11.2 R66.1 R91.1 U4.G7(VP_0)
NetR45_2: R45.2 U4.E6(VCCBATT_0)
NetR46_2: R46.2 U4.K6(PROGRAM_B_0)
NetR47_2: R47.2 U4.D5(INIT_B_0)

Not connected (* = marked no-connect by the designer): U4 B13(VCCO_MIO1_501) F11(VCCO_35) H15(VCCO_35)

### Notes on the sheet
- NOTE CHANGE LED PACKAGE
- ZYNQ POWER
- ZYNQ BANK 0
- PLACE NEAR XC7Z010 (VCCO_DDR)
- VCC AUX DECOUPLING
- VCC INT DECOUPLING
- VCCO PAUX DECOUPLING
- PLACE NEAR XC7Z010 (VCC_AUX)
- PLACE NEAR XC7Z010 (VCC_INT)
- PLACE NEAR XC7Z010 (VCCO_MIO0)
- VCC PINT DECOUPLING
- VCC PLL FILTERING
- VCC PAUX DECOUPLING
- PLACE NEAR XC7Z010 (VCC_PINT)
- (near E1) PLACE NEAR XC7Z010 (VCC_PLL)
- PLACE NEAR XC7Z010 (VCC_PAUX)
- PlutoV2 Schematic
- A
- R.Pender

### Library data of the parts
C49 C54 C64 C71 C76 = CMP-1662-00011-2: as C100 on sheet DDR3
C50 C51 C55-C59 C66-C70 C72-C75 C78 C90 C93 C174 C178 = CMP-2000-05437-2: as C86 on sheet DDR3
C52 C60 C98 = GRM033R61C104ME84D: as C46 on sheet USB
C53 C61 = GRM033R71A103KA01D: as C187 on sheet USB
C65 C85 = CMP-2000-06498-1: High Value Multilayer Ceramic Capacitor, 47 uF, +/-20%, 6.3 V, -55 to 85 degC, 2-Pin SMD (0805), RoHS, Tape and Reel; Manufacturer: Taiyo Yuden; PCN Part Number: X5R,X7RDielectrics23/Jan/2008; Kits: 587-1797-KIT-ND-KITCAPCERHICAP0603&0805S; Temperature Coefficient: X5R; Tolerance: ±20%; Online Catalog: MSeries; Other Names: 587-1779-1; Capacitance: 47µF; Voltage - Rated: 6.3V; Catalog Drawings: xMKSeries_0805_1.25
DS1 DS2 = LED3: Typical BLUE SiC LED
E1 E5 E6 = CMP-2000-05399-1: Chip Bead for Power Line, 100 Ohm, +/- 25%, 4 A, -55 to 125 degC, 0805 (2012 Metric), RoHS, Tape and Reel; Manufacturer: TDK; Maximum DC Resistance: 20mOhms; Test Frequency: 100MHz; Impedance: 100Ohms; Case Width: 1.25mm; Case Length: 2mm; Maximum DC Current: 4A; Case Height: 0.85mm
Q1 Q4 = CMP-1058-00767-1: Power MOSFET, 200 mA, 50 V, N-Channel, 3-Pin SOT-23, Pb-Free, Tape and Reel; Manufacturer: On Semiconductor; PD Max (W): 0.225; Coss Typ (pF): 12; V(BR)DSS Min (V): 50; VGS Max (V): 20; Channel Polarity: N Channel; Configuration: Single; VGS(th) Max (V): 1.5; Ciss Typ (pF): 40; Crss Typ (pF): 3.5; ID Max (A): 0.2
R11 R46 R47 R66 R75 R91 = ERJ2RK: as R13 on sheet USB
R45 = CMP-2002-05896-1: as R43 on sheet DDR3
R48 R87 = ERJ2GE: as R12 on sheet USB
U4 = XC7Z010-1CLG225C: as U4 on sheet USB

## Sheet ZYNQ 34_35 and QPSI.SchDoc
size A3; SheetNumber: 5; SheetTotal: 13
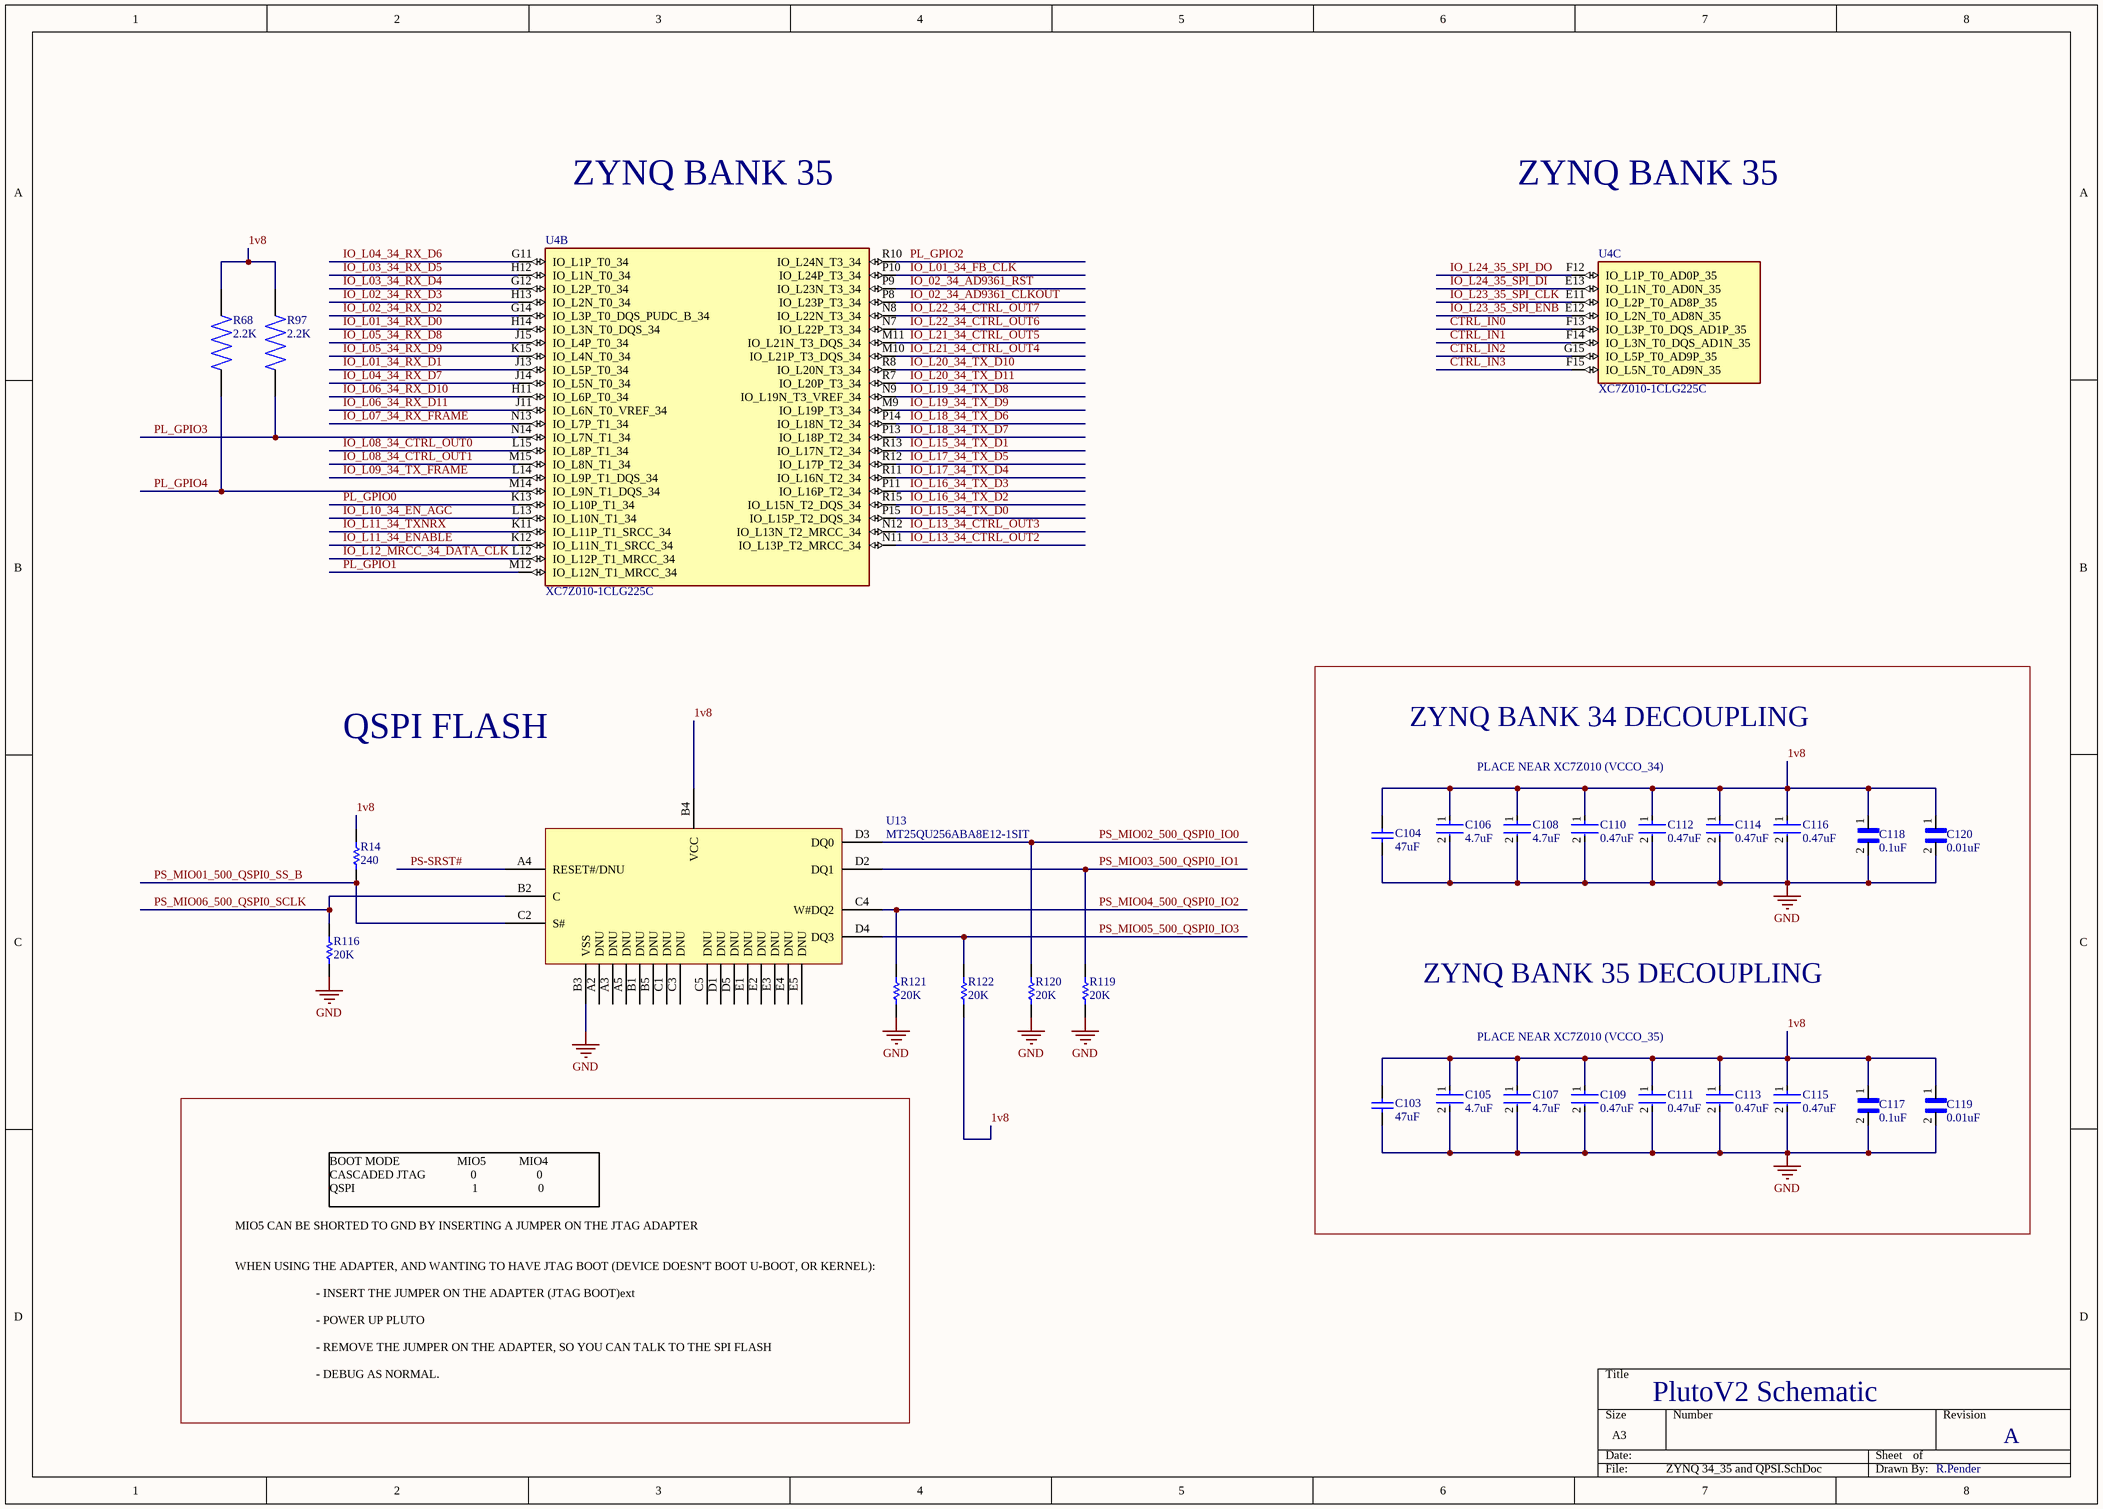
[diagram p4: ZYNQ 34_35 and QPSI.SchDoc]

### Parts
C103  47uF  [TAYO-JMK212BBJ476MG-T_L]
C104  47uF  [TAYO-JMK212BBJ476MG-T_L]
C105  4.7uF  [FP-C1005-050-0_15-IPC_C]
C106  4.7uF  [FP-C1005-050-0_15-IPC_C]
C107  4.7uF  [FP-C1005-050-0_15-IPC_C]
C108  4.7uF  [FP-C1005-050-0_15-IPC_C]
C109  0.47uF  [FP-C1005-050-0_15-MFG]
C110  0.47uF  [FP-C1005-050-0_15-MFG]
C111  0.47uF  [FP-C1005-050-0_15-MFG]
C112  0.47uF  [FP-C1005-050-0_15-MFG]
C113  0.47uF  [FP-C1005-050-0_15-MFG]
C114  0.47uF  [FP-C1005-050-0_15-MFG]
C115  0.47uF  [FP-C1005-050-0_15-MFG]
C116  0.47uF  [FP-C1005-050-0_15-MFG]
C117  0.1uF  [CAPC0603X33N]
C118  0.1uF  [CAPC0603X33N]
C119  0.01uF  [CAPC0603X33N]
C120  0.01uF  [CAPC0603X33N]
R14  240  [2-0402]
R68  2.2K  [RESC1005X35N]
R97  2.2K  [RESC1005X35N]
R116  20K  [2-0402]
R119  20K  [2-0402]
R120  20K  [2-0402]
R121  20K  [2-0402]
R122  20K  [2-0402]
U4  XC7Z010-1CLG225C  [BGA225C80P15X15_1300X1300X150]  (parts B,C of 6)
U13  MT25QU256ABA8E12-1SIT  [BGA25C100P5X5_800X600X120N]

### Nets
GND: C103.2 C104.2 C105.2 C106.2 C107.2 C108.2 C109.2 C110.2 C111.2 C112.2 C113.2 C114.2 C115.2 C116.2 C117.2 C118.2 C119.2 C120.2 R116.2 R119.2 R120.2 R121.2 U13.B3(VSS)
1v8: C103.1 C104.1 C105.1 C106.1 C107.1 C108.1 C109.1 C110.1 C111.1 C112.1 C113.1 C114.1 C115.1 C116.1 C117.1 C118.1 C119.1 C120.1 R14.1 R68.2 R97.2 R122.2 U13.B4(VCC)
CTRL_IN0: U4.F13(IO_L3P_T0_DQS_AD1P_35)
CTRL_IN1: U4.F14(IO_L3N_T0_DQS_AD1N_35)
CTRL_IN2: U4.G15(IO_L5P_T0_AD9P_35)
CTRL_IN3: U4.F15(IO_L5N_T0_AD9N_35)
IO_02_34_AD9361_CLKOUT: U4.P8(IO_L23P_T3_34)
IO_02_34_AD9361_RST: U4.P9(IO_L23N_T3_34)
IO_L01_34_FB_CLK: U4.P10(IO_L24P_T3_34)
IO_L01_34_RX_D0: U4.H14(IO_L3N_T0_DQS_34)
IO_L01_34_RX_D1: U4.J13(IO_L5P_T0_34)
IO_L02_34_RX_D2: U4.G14(IO_L3P_T0_DQS_PUDC_B_34)
IO_L02_34_RX_D3: U4.H13(IO_L2N_T0_34)
IO_L03_34_RX_D4: U4.G12(IO_L2P_T0_34)
IO_L03_34_RX_D5: U4.H12(IO_L1N_T0_34)
IO_L04_34_RX_D6: U4.G11(IO_L1P_T0_34)
IO_L04_34_RX_D7: U4.J14(IO_L5N_T0_34)
IO_L05_34_RX_D8: U4.J15(IO_L4P_T0_34)
IO_L05_34_RX_D9: U4.K15(IO_L4N_T0_34)
IO_L06_34_RX_D10: U4.H11(IO_L6P_T0_34)
IO_L06_34_RX_D11: U4.J11(IO_L6N_T0_VREF_34)
IO_L07_34_RX_FRAME: U4.N13(IO_L7P_T1_34)
IO_L08_34_CTRL_OUT0: U4.L15(IO_L8P_T1_34)
IO_L08_34_CTRL_OUT1: U4.M15(IO_L8N_T1_34)
IO_L09_34_TX_FRAME: U4.L14(IO_L9P_T1_DQS_34)
IO_L10_34_EN_AGC: U4.L13(IO_L10N_T1_34)
IO_L11_34_ENABLE: U4.K12(IO_L11N_T1_SRCC_34)
IO_L11_34_TXNRX: U4.K11(IO_L11P_T1_SRCC_34)
IO_L12_MRCC_34_DATA_CLK: U4.L12(IO_L12P_T1_MRCC_34)
IO_L13_34_CTRL_OUT2: U4.N11(IO_L13P_T2_MRCC_34)
IO_L13_34_CTRL_OUT3: U4.N12(IO_L13N_T2_MRCC_34)
IO_L15_34_TX_D0: U4.P15(IO_L15P_T2_DQS_34)
IO_L15_34_TX_D1: U4.R13(IO_L17N_T2_34)
IO_L16_34_TX_D2: U4.R15(IO_L15N_T2_DQS_34)
IO_L16_34_TX_D3: U4.P11(IO_L16P_T2_34)
IO_L17_34_TX_D4: U4.R11(IO_L16N_T2_34)
IO_L17_34_TX_D5: U4.R12(IO_L17P_T2_34)
IO_L18_34_TX_D6: U4.P14(IO_L18N_T2_34)
IO_L18_34_TX_D7: U4.P13(IO_L18P_T2_34)
IO_L19_34_TX_D8: U4.N9(IO_L19N_T3_VREF_34)
IO_L19_34_TX_D9: U4.M9(IO_L19P_T3_34)
IO_L20_34_TX_D10: U4.R8(IO_L20N_T3_34)
IO_L20_34_TX_D11: U4.R7(IO_L20P_T3_34)
IO_L21_34_CTRL_OUT4: U4.M10(IO_L21P_T3_DQS_34)
IO_L21_34_CTRL_OUT5: U4.M11(IO_L21N_T3_DQS_34)
IO_L22_34_CTRL_OUT6: U4.N7(IO_L22P_T3_34)
IO_L22_34_CTRL_OUT7: U4.N8(IO_L22N_T3_34)
IO_L23_35_SPI_CLK: U4.E11(IO_L2P_T0_AD8P_35)
IO_L23_35_SPI_ENB: U4.E12(IO_L2N_T0_AD8N_35)
IO_L24_35_SPI_DI: U4.E13(IO_L1N_T0_AD0N_35)
IO_L24_35_SPI_DO: U4.F12(IO_L1P_T0_AD0P_35)
PL_GPIO0: U4.K13(IO_L10P_T1_34)
PL_GPIO1: U4.M12(IO_L12N_T1_MRCC_34)
PL_GPIO2: U4.R10(IO_L24N_T3_34)
PL_GPIO3: R97.1 U4.N14(IO_L7N_T1_34)
PL_GPIO4: R68.1 U4.M14(IO_L9N_T1_DQS_34)
PS-SRST#: U13.A4(RESET#/DNU)
PS_MIO01_500_QSPI0_SS_B: R14.2 U13.C2(S#)
PS_MIO02_500_QSPI0_IO0: R120.1 U13.D3(DQ0)
PS_MIO03_500_QSPI0_IO1: R119.1 U13.D2(DQ1)
PS_MIO04_500_QSPI0_IO2: R121.1 U13.C4(W#DQ2)
PS_MIO05_500_QSPI0_IO3: R122.1 U13.D4(DQ3)
PS_MIO06_500_QSPI0_SCLK: R116.1 U13.B2(C)

Not connected (* = marked no-connect by the designer): U13 A2(DNU) A3(DNU) A5(DNU) B1(DNU) B5(DNU) C1(DNU) C3(DNU) C5(DNU) D1(DNU) D5(DNU) E1(DNU) E2(DNU) E3(DNU) E4(DNU) E5(DNU)

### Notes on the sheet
- ZYNQ BANK 35
- QSPI FLASH
- ZYNQ BANK 34 DECOUPLING
- PLACE NEAR XC7Z010 (VCCO_34)
- ZYNQ BANK 35 DECOUPLING
- PLACE NEAR XC7Z010 (VCCO_35)
- MIO5 CAN BE SHORTED TO GND BY INSERTING A JUMPER ON THE JTAG ADAPTER
- BOOT MODE                   MIO5           MIO4                      CASCADED JTAG               0                    0                                              QSPI                                       1                    0
- WHEN USING THE ADAPTER, AND WANTING TO HAVE JTAG BOOT (DEVICE DOESN'T BOOT U-BOOT, OR KERNEL):
- - INSERT THE JUMPER ON THE ADAPTER (JTAG BOOT)ext
- - POWER UP PLUTO
- - REMOVE THE JUMPER ON THE ADAPTER, SO YOU CAN TALK TO THE SPI FLASH
- - DEBUG AS NORMAL.
- PlutoV2 Schematic
- A
- R.Pender

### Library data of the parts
C103 C104 = CMP-2000-06498-1: as C65 on sheet ZYNQ JTAG and Decoupling
C105-C116 = CMP-2000-05437-2: as C86 on sheet DDR3
C117 C118 = GRM033R61C104ME84D: as C46 on sheet USB
C119 C120 = GRM033R71A103KA01D: as C187 on sheet USB
R14 R116 R119-R122 = ERJ2RK: as R13 on sheet USB
R68 R97 = CRCW04022K20FKEDC: 2.2 kOhms Â±1% 0.063W, 1/16W Chip Resistor 0402 _1005 Metric_ Thick Film; MF: Vishay
U4 = XC7Z010-1CLG225C: as U4 on sheet USB
U13 = Component_1

## Sheet AD9363.SchDoc
size A3; SheetNumber: 6; SheetTotal: 13; SPICEModelCachePHHWHPTQ: <root> / <DocumentId>PHHWHPTQ</DocumentId> / <CacheFrame Number="0"> / <Model Name="emk105bj105_v-f" Kind="CKT"> / <Text>* EMK105BJ105_V-F     SPICE MODEL  ( General Type ) / *-------------------------------------------------------------------------------------------------------- / * Model Generated by TAIYO YUDEN Corporation (http://www.ty-top.com) / * Version 1.0 / * TAIYO YUDEN Control No. 170508_130520 / * Copyright(c) 2012 TAIYO YUDEN CO.,LTD. All Rights Reserved. / *-------------------------------------------------------------------------------------------------------- / * / * Products Name : Multilayer Ceramic Capacitors / * / * Characteristics : / *     Capacitance : 1 uF , Rated Voltage : 16V , TCC : X5R / *     Case Size : 1.0 x 0.5 / 0.039 x 0.02 [mm/inch] , Thickness : 0.5 / 0.02 [mm/inch] / *     (Conditions: Temperature = 25 degC , DC Bias Current/Voltage = 0A / 0V) / * / * Frequency Range : 40Hz - 3GHz / * / * External Node Assignments : / * / *  1  o---¦ ¦---o  2 / * / *-------------------------------------------------------------------------------------------------------- / .SubCkt EMK105BJ105_V-F 1 2 / **************************** / C0 1 110 0.68309u / Cm 1 101 0.26053u / C1 101 102 0.94076u / Rc1 101 102 1.9029k / C2 102 103 0.66707u / Rc2 102 103 120.36 / C3 103 110 0.57203u / Rc3 103 110 2.1097 / C2m 1 301 0.1871u / C21 301 302 3.2494u / Rc21 301 302 1.1117k / C22 302 303 2.1014u / Rc22 302 303 1.484k / C23 303 304 2.1172u / Rc23 303 304 1.3876k / C24 304 305 0.75729u / Rc24 304 305 332.59 / C25 305 306 0.94401u / Rc25 305 306 249.09 / C26 306 307 0.34674u / Rc26 306 307 28.352 / C27 307 308 0.37158u / Rc27 307 308 19.989 / C28 308 309 0.17933u / Rc28 308 309 31.748 / C29 309 110 0.016445u / Rc29 309 110 1.0592 / Rp0 1 110 100Meg / L0 110 120 0.2216n / Lm 120 130 0.1509n / L1 120 121 0.12659n / RL1 121 130 0.85161 / L2 120 122 0.15996n / RL2 122 130 0.42469 / L3 120 123 7.9543n / RL3 123 130 0.54643m / CR 120 124 0.24334u / LR 124 125 0.090738n / RR 125 130 68.076m / CL 130 140 2.7354p / LL 130 140 0.10762n / RL 130 140 50.614 / Rs 140 2 7.5416m / **************************** / .ends EMK105BJ105_V-F</Text> / </Model> / </CacheFrame> / </root>
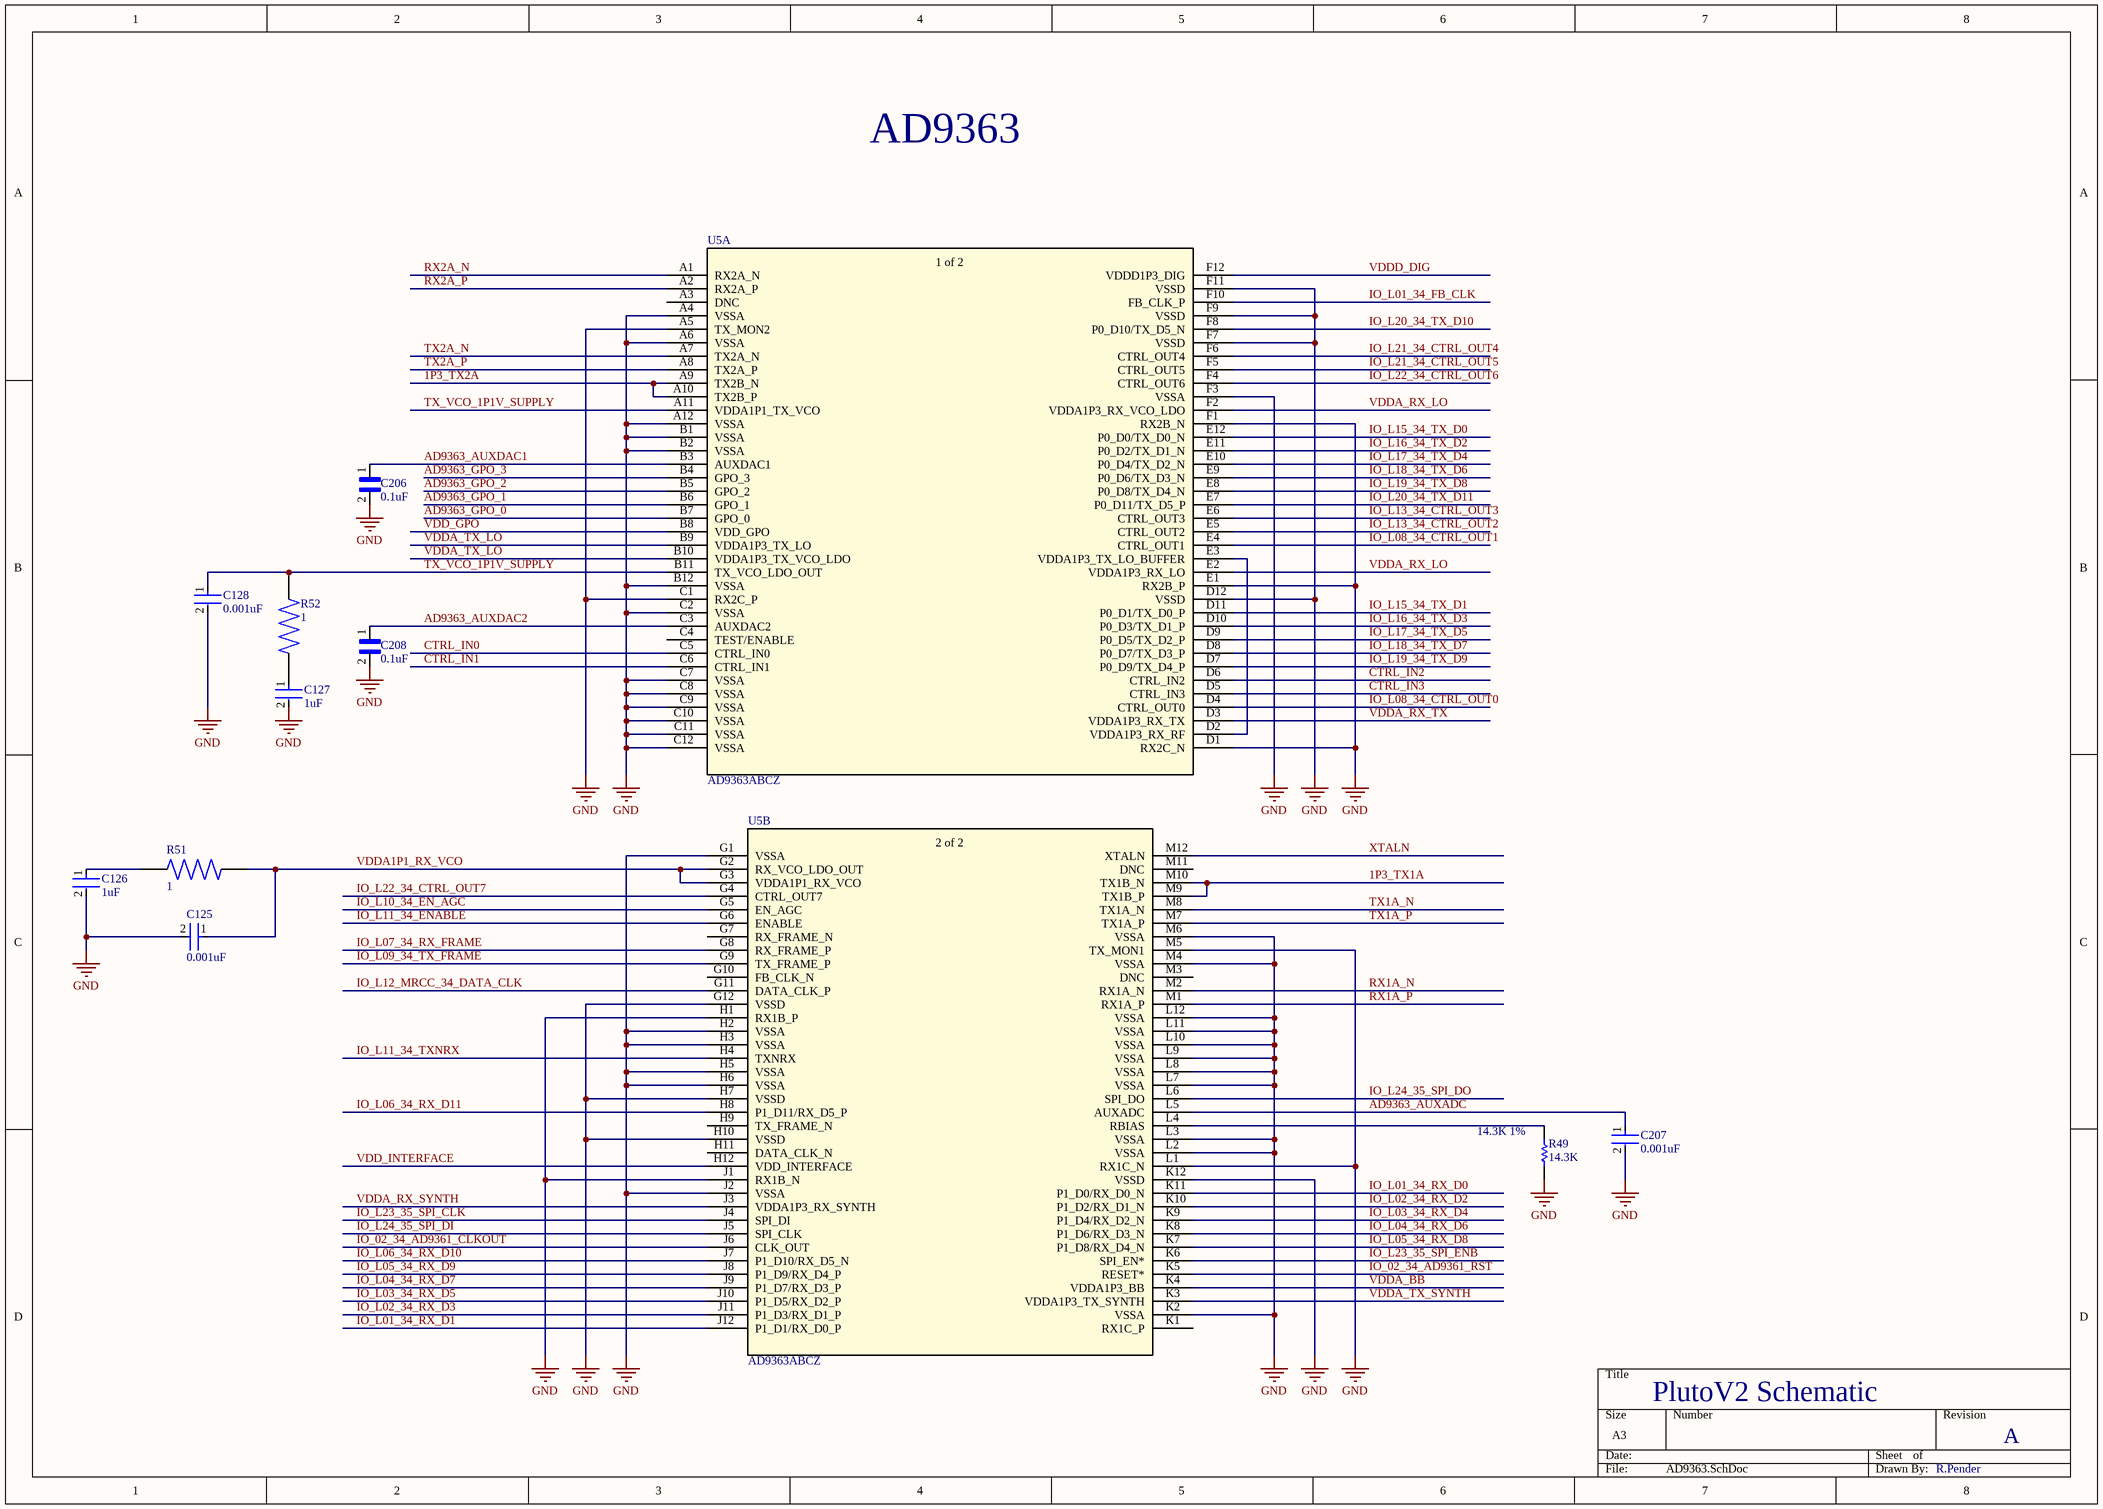
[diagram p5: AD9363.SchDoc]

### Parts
C125  0.001uF  [FP-GRM033-0_03-MFG]
C126  1uF  [FP-0402-L_1_0_0_05-W_0_5-IPC_A]
C127  1uF  [FP-0402-L_1_0_0_05-W_0_5-IPC_A]
C128  0.001uF  [FP-GRM033-0_03-MFG]
C206  0.1uF  [CAPC0603X33N]
C207  0.001uF  [FP-GRM033-0_03-MFG]
C208  0.1uF  [CAPC0603X33N]
R49  14.3K  [RESC0603X26X15NL03T05]
R51  1  [RESC0603X26N]
R52  1  [RESC0603X26N]
U5  AD9363ABCZ  [BC_144_7_ADI]  (parts A,B of 2)

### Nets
GND: C125.2 C126.2 C127.2 C128.2 C206.2 C207.2 C208.2 R49.2 U5.A4(VSSA) U5.A5(TX_MON2) U5.A6(VSSA) U5.A12(VSSA) U5.B1(VSSA) U5.B2(VSSA) U5.B12(VSSA) U5.C1(RX2C_P) U5.C2(VSSA) U5.C7(VSSA) U5.C8(VSSA) U5.C9(VSSA) U5.C10(VSSA) U5.C11(VSSA) U5.C12(VSSA) U5.D1(RX2C_N) U5.D12(VSSD) U5.E1(RX2B_P) U5.F1(RX2B_N) U5.F3(VSSA) U5.F7(VSSD) U5.F9(VSSD) U5.F11(VSSD) U5.G1(VSSA) U5.G12(VSSD) U5.H1(RX1B_P) U5.H2(VSSA) U5.H3(VSSA) U5.H5(VSSA) U5.H6(VSSA) U5.H7(VSSD) U5.H10(VSSD) U5.J1(RX1B_N) U5.J2(VSSA) U5.K2(VSSA) U5.K12(VSSD) U5.L1(RX1C_N) U5.L2(VSSA) U5.L3(VSSA) U5.L7(VSSA) U5.L8(VSSA) U5.L9(VSSA) U5.L10(VSSA) U5.L11(VSSA) U5.L12(VSSA) U5.M4(VSSA) U5.M5(TX_MON1) U5.M6(VSSA)
1P3_TX1A: U5.A9(TX2B_N) U5.A10(TX2B_P) U5.F12(VDDD1P3_DIG) U5.J3(VDDA1P3_RX_SYNTH) U5.K4(VDDA1P3_BB) U5.M9(TX1B_P) U5.M10(TX1B_N)  [also labelled 1P3_TX2A, VDDA_BB, VDDA_RX_SYNTH, VDDD_DIG]  [project net 1P3_SUPPLY_B]
AD9363_AUXADC: C207.1 U5.L5(AUXADC)
AD9363_AUXDAC1: C206.1 U5.B3(AUXDAC1)
AD9363_AUXDAC2: C208.1 U5.C3(AUXDAC2)
AD9363_GPO_0: U5.B7(GPO_0)
AD9363_GPO_1: U5.B6(GPO_1)
AD9363_GPO_2: U5.B5(GPO_2)
AD9363_GPO_3: U5.B4(GPO_3)
CTRL_IN0: U5.C5(CTRL_IN0)
CTRL_IN1: U5.C6(CTRL_IN1)
CTRL_IN2: U5.D6(CTRL_IN2)
CTRL_IN3: U5.D5(CTRL_IN3)
IO_02_34_AD9361_CLKOUT: U5.J6(CLK_OUT)
IO_02_34_AD9361_RST: U5.K5(RESET*)
IO_L01_34_FB_CLK: U5.F10(FB_CLK_P)
IO_L01_34_RX_D0: U5.K11(P1_D0/RX_D0_N)
IO_L01_34_RX_D1: U5.J12(P1_D1/RX_D0_P)
IO_L02_34_RX_D2: U5.K10(P1_D2/RX_D1_N)
IO_L02_34_RX_D3: U5.J11(P1_D3/RX_D1_P)
IO_L03_34_RX_D4: U5.K9(P1_D4/RX_D2_N)
IO_L03_34_RX_D5: U5.J10(P1_D5/RX_D2_P)
IO_L04_34_RX_D6: U5.K8(P1_D6/RX_D3_N)
IO_L04_34_RX_D7: U5.J9(P1_D7/RX_D3_P)
IO_L05_34_RX_D8: U5.K7(P1_D8/RX_D4_N)
IO_L05_34_RX_D9: U5.J8(P1_D9/RX_D4_P)
IO_L06_34_RX_D10: U5.J7(P1_D10/RX_D5_N)
IO_L06_34_RX_D11: U5.H8(P1_D11/RX_D5_P)
IO_L07_34_RX_FRAME: U5.G8(RX_FRAME_P)
IO_L08_34_CTRL_OUT0: U5.D4(CTRL_OUT0)
IO_L08_34_CTRL_OUT1: U5.E4(CTRL_OUT1)
IO_L09_34_TX_FRAME: U5.G9(TX_FRAME_P)
IO_L10_34_EN_AGC: U5.G5(EN_AGC)
IO_L11_34_ENABLE: U5.G6(ENABLE)
IO_L11_34_TXNRX: U5.H4(TXNRX)
IO_L12_MRCC_34_DATA_CLK: U5.G11(DATA_CLK_P)
IO_L13_34_CTRL_OUT2: U5.E5(CTRL_OUT2)
IO_L13_34_CTRL_OUT3: U5.E6(CTRL_OUT3)
IO_L15_34_TX_D0: U5.E12(P0_D0/TX_D0_N)
IO_L15_34_TX_D1: U5.D11(P0_D1/TX_D0_P)
IO_L16_34_TX_D2: U5.E11(P0_D2/TX_D1_N)
IO_L16_34_TX_D3: U5.D10(P0_D3/TX_D1_P)
IO_L17_34_TX_D4: U5.E10(P0_D4/TX_D2_N)
IO_L17_34_TX_D5: U5.D9(P0_D5/TX_D2_P)
IO_L18_34_TX_D6: U5.E9(P0_D6/TX_D3_N)
IO_L18_34_TX_D7: U5.D8(P0_D7/TX_D3_P)
IO_L19_34_TX_D8: U5.E8(P0_D8/TX_D4_N)
IO_L19_34_TX_D9: U5.D7(P0_D9/TX_D4_P)
IO_L20_34_TX_D10: U5.F8(P0_D10/TX_D5_N)
IO_L20_34_TX_D11: U5.E7(P0_D11/TX_D5_P)
IO_L21_34_CTRL_OUT4: U5.F6(CTRL_OUT4)
IO_L21_34_CTRL_OUT5: U5.F5(CTRL_OUT5)
IO_L22_34_CTRL_OUT6: U5.F4(CTRL_OUT6)
IO_L22_34_CTRL_OUT7: U5.G4(CTRL_OUT7)
IO_L23_35_SPI_CLK: U5.J4(SPI_DI)
IO_L23_35_SPI_ENB: U5.K6(SPI_EN*)
IO_L24_35_SPI_DI: U5.J5(SPI_CLK)
IO_L24_35_SPI_DO: U5.L6(SPI_DO)
RX1A_N: U5.M2(RX1A_N)
RX1A_P: U5.M1(RX1A_P)
RX2A_N: U5.A1(RX2A_N)
RX2A_P: U5.A2(RX2A_P)
TX1A_N: U5.M8(TX1A_N)
TX1A_P: U5.M7(TX1A_P)
TX2A_N: U5.A7(TX2A_N)
TX2A_P: U5.A8(TX2A_P)
TX_VCO_1P1V_SUPPLY: C128.1 R52.1 U5.A11(VDDA1P1_TX_VCO) U5.B11(TX_VCO_LDO_OUT)
VDD_GPO: U5.B8(VDD_GPO)  [project net 3P3V]
VDD_INTERFACE: U5.H12(VDD_INTERFACE)
VDDA1P1_RX_VCO: C125.1 R51.2 U5.G2(RX_VCO_LDO_OUT) U5.G3(VDDA1P1_RX_VCO)
VDDA_RX_LO: U5.B9(VDDA1P3_TX_LO) U5.B10(VDDA1P3_TX_VCO_LDO) U5.D3(VDDA1P3_RX_TX) U5.E2(VDDA1P3_RX_LO) U5.F2(VDDA1P3_RX_VCO_LDO) U5.K3(VDDA1P3_TX_SYNTH)  [also labelled VDDA_RX_TX, VDDA_TX_LO, VDDA_TX_SYNTH]  [project net 1P3_SUPPLY_A]
XTALN: U5.M12(XTALN)
NetC126_1: C126.1 R51.1
NetC127_1: C127.1 R52.2
NetR49_1: R49.1 U5.L4(RBIAS)
NetU5_D2: U5.D2(VDDA1P3_RX_RF) U5.E3(VDDA1P3_TX_LO_BUFFER)

Not connected (* = marked no-connect by the designer): U5 A3(DNC) C4(TEST/ENABLE) G7(RX_FRAME_N) G10(FB_CLK_N) H9(TX_FRAME_N) H11(DATA_CLK_N) K1(RX1C_P) M3(DNC) M11(DNC)

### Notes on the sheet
- AD9363
- (near R49) 14.3K 1%
- PlutoV2 Schematic
- A
- R.Pender

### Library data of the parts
C125 C128 C207 = CMP-2010-01706-2: Chip Multilayer Ceramic Capacitors for General Purpose, 0201, 1000pF, X7R, 15%, 10%, 25V; Capacitance: 1nF
C126 C127 = CMP-14477-000104-2: None; Tolerance: 10%; Voltage Rating: 16V; Dielectric: X5R
C206 C208 = GRM033R61C104ME84D: as C46 on sheet USB
R49 = CMP-1010-00545-2: Manufacturer: Panasonic; Part Number: ERJ-1GNF1432C
R51 R52 = RMCF0201FT1R00
U5 = AD9363ABCZ: No Description Available; Mfr_Name: Analog Devices Inc

## Sheet RF FRONTEND.SchDoc
size A3; SheetNumber: 7; SheetTotal: 12
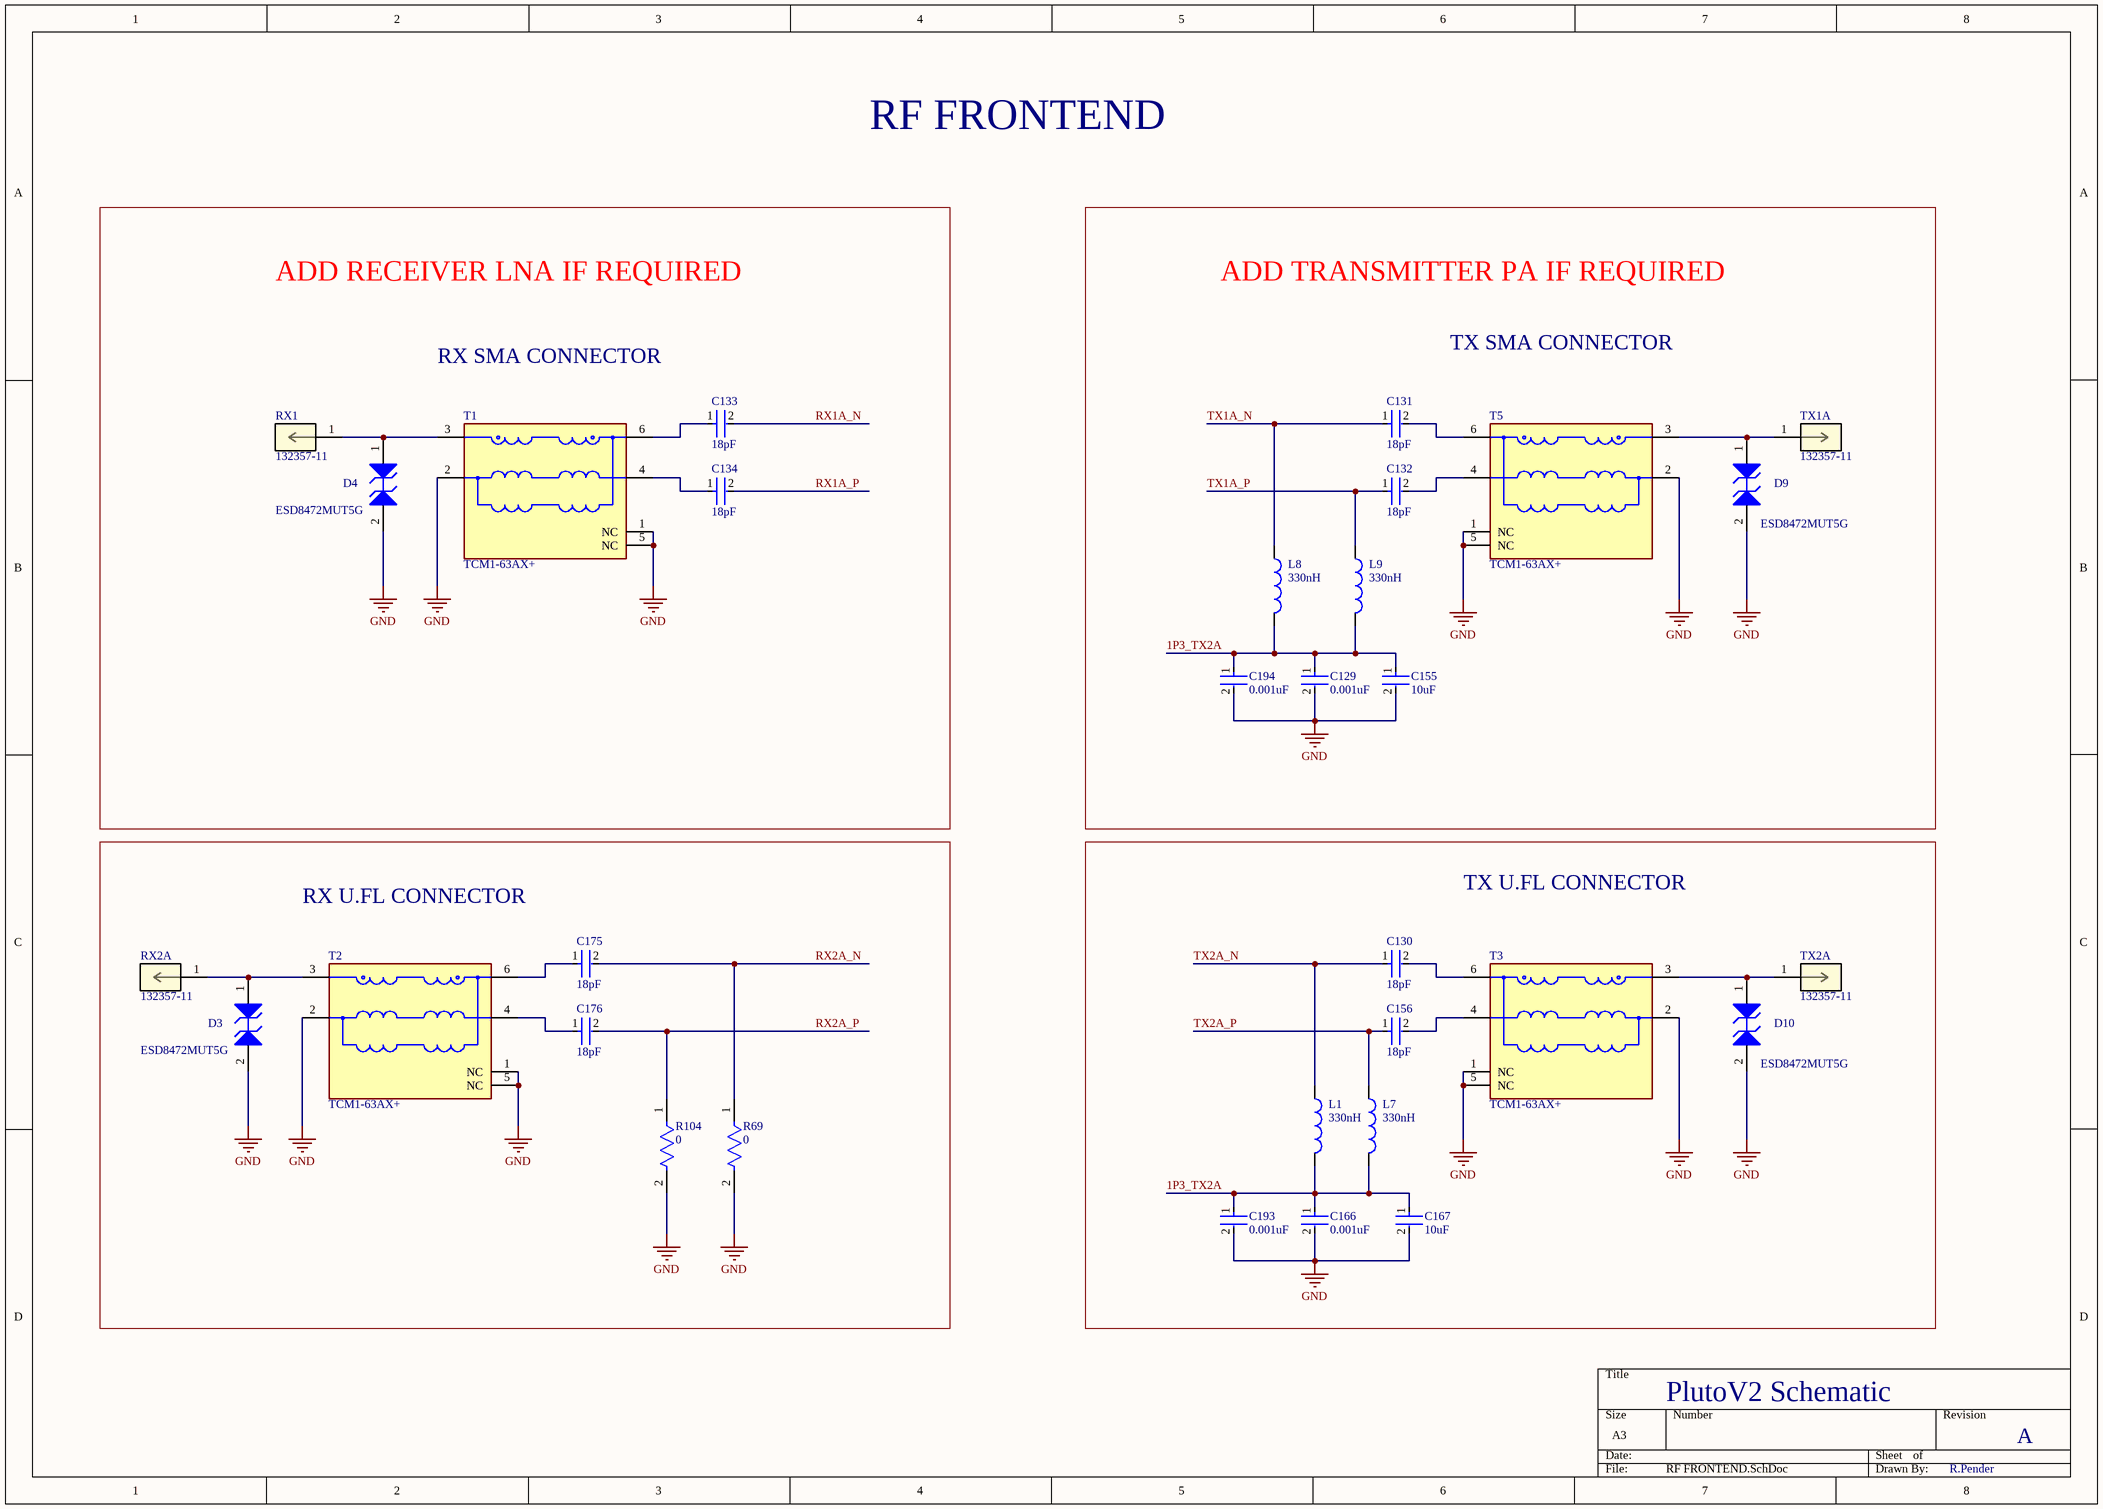
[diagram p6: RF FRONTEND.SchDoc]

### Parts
C129  0.001uF  [FP-GRM033-0_03-MFG]
C130  18pF  [FP-GRM033-0_03-IPC_A]
C131  18pF  [FP-GRM033-0_03-IPC_A]
C132  18pF  [FP-GRM033-0_03-IPC_A]
C133  18pF  [FP-GRM033-0_03-IPC_A]
C134  18pF  [FP-GRM033-0_03-IPC_A]
C155  10uF  [FP-GRM188-0_1-e0_2_0_55-IPC_C]
C156  18pF  [FP-GRM033-0_03-IPC_A]
C166  0.001uF  [FP-GRM033-0_03-MFG]
C167  10uF  [FP-GRM188-0_1-e0_2_0_55-IPC_C]
C175  18pF  [FP-GRM033-0_03-IPC_A]
C176  18pF  [FP-GRM033-0_03-IPC_A]
C193  0.001uF  [FP-GRM033-0_03-MFG]
C194  0.001uF  [FP-GRM033-0_03-MFG]
D3  ESD8472MUT5G  [ONSC-X3DFN-2-152AF-01_V]
D4  ESD8472MUT5G  [ONSC-X3DFN-2-152AF-01_V]
D9  ESD8472MUT5G  [ONSC-X3DFN-2-152AF-01_V]
D10  ESD8472MUT5G  [ONSC-X3DFN-2-152AF-01_V]
L1  330nH  [INDC2317X140N]
L7  330nH  [INDC2317X140N]
L8  330nH  [INDC2317X140N]
L9  330nH  [INDC2317X140N]
R69  0  [FP-ERJ1GN-MFG]
R104  0  [FP-ERJ1GN-MFG]
RX1  132357-11  [CONN_132357-11_AMP]
RX2A  132357-11  [CONN_132357-11_AMP]
T1  TCM1-63AX+  [FP-TCM1-63AX+-MFG]
T2  TCM1-63AX+  [FP-TCM1-63AX+-MFG]
T3  TCM1-63AX+  [FP-TCM1-63AX+-MFG]
T5  TCM1-63AX+  [FP-TCM1-63AX+-MFG]
TX1A  132357-11  [CONN_132357-11_AMP]
TX2A  132357-11  [CONN_132357-11_AMP]

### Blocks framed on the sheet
ADD RECEIVER LNA IF REQUIRED: C133 C134 D4 RX1 T1
ADD TRANSMITTER PA IF REQUIRED: C129 C131 C132 C155 C194 D9 L8 L9 T5 TX1A
RX U.FL CONNECTOR: C175 C176 D3 R69 R104 RX2A T2
TX U.FL CONNECTOR: C130 C156 C166 C167 C193 D10 L1 L7 T3 TX2A

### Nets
GND: C129.2 C155.2 C166.2 C167.2 C193.2 C194.2 D3.2(A2) D4.2(A2) D9.2(A2) D10.2(A2) R69.2 R104.2 T1.1(NC) T1.2(GND) T1.5(NC) T2.1(NC) T2.2(GND) T2.5(NC) T3.1(NC) T3.2(GND) T3.5(NC) T5.1(NC) T5.2(GND) T5.5(NC)
1P3_TX2A: C129.1 C155.1 C166.1 C167.1 C193.1 C194.1 L1.2 L7.2 L8.2 L9.2  [project net 1P3_SUPPLY_B]
RX1A_N: C133.2
RX1A_P: C134.2
RX2A_N: C175.2 R69.1
RX2A_P: C176.2 R104.1
TX1A_N: C131.1 L8.1
TX1A_P: C132.1 L9.1
TX2A_N: C130.1 L1.1
TX2A_P: C156.1 L7.1
NetC130_2: C130.2 T3.6(SECONDARY_DOT)
NetC131_2: C131.2 T5.6(SECONDARY_DOT)
NetC132_2: C132.2 T5.4(SECONDARY)
NetC133_1: C133.1 T1.6(SECONDARY_DOT)
NetC134_1: C134.1 T1.4(SECONDARY)
NetC156_2: C156.2 T3.4(SECONDARY)
NetC175_1: C175.1 T2.6(SECONDARY_DOT)
NetC176_1: C176.1 T2.4(SECONDARY)
NetD3_1: D3.1(A1) RX2A.1 T2.3(PRIMARY_DOT)
NetD4_1: D4.1(A1) RX1.1 T1.3(PRIMARY_DOT)
NetD9_1: D9.1(A1) T5.3(PRIMARY_DOT) TX1A.1
NetD10_1: D10.1(A1) T3.3(PRIMARY_DOT) TX2A.1

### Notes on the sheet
- RF FRONTEND
- RX SMA CONNECTOR
- TX SMA CONNECTOR
- PlutoV2 Schematic
- A
- R.Pender

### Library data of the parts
C129 C166 C193 C194 = CMP-2010-01706-2: as C125 on sheet AD9363
C130-C134 C156 C175 C176 = CMP-2010-01507-2: Chip Multilayer Ceramic Capacitors for General Purpose, 0201, 18pF, C0G, 30ppm/°C, 5%, 50V
C155 C167 = CMP-2006-02792-2: as C79 on sheet DDR3
D3 D4 D9 D10 = CMP-1063-00281-1: Ultra-Low Capacitance ESD Protection, Micro-Packaged Diode for ESD Protection, 2-Pin X3DFN, Pb-Free, Tape and Reel; Manufacturer: On Semiconductor; IR Max (uA): 0.05; C Max (pF): 0.3; V(BR) Min (V): 7; VRWM Max (V): 5.3; Number of Lines: 1; Direction: Bidirectional
L1 L7-L9 = Inductor: Code_IEC: 1005; Value: 10mH
R69 R104 = CMP-1010-00001-3: RES SMD 0 OHM JUMPER 1/20W 0201; Temperature Coefficient: 600ppm/°C; Max Power Dissipation: 50mW; Resistance: 0R; Voltage Rating: 25V; Tolerance: 1%
RX1 RX2A TX1A TX2A = 132357-11: No Description Available; Mfr_Name: Amphenol ICC
T1-T3 T5 = CMP-199822-000001-1: 1:1 CORE & WIRE Transformer, 10 - 6000 MHz, 50Ω; Manufacturer: Mini-Circuits; Insertion Loss: 1.16-1.8dB; Return Loss: 9.42-16.9dB

## Sheet CONNECTORS_SELECTORS.SchDoc
size A3; SheetNumber: 8; SheetTotal: 13
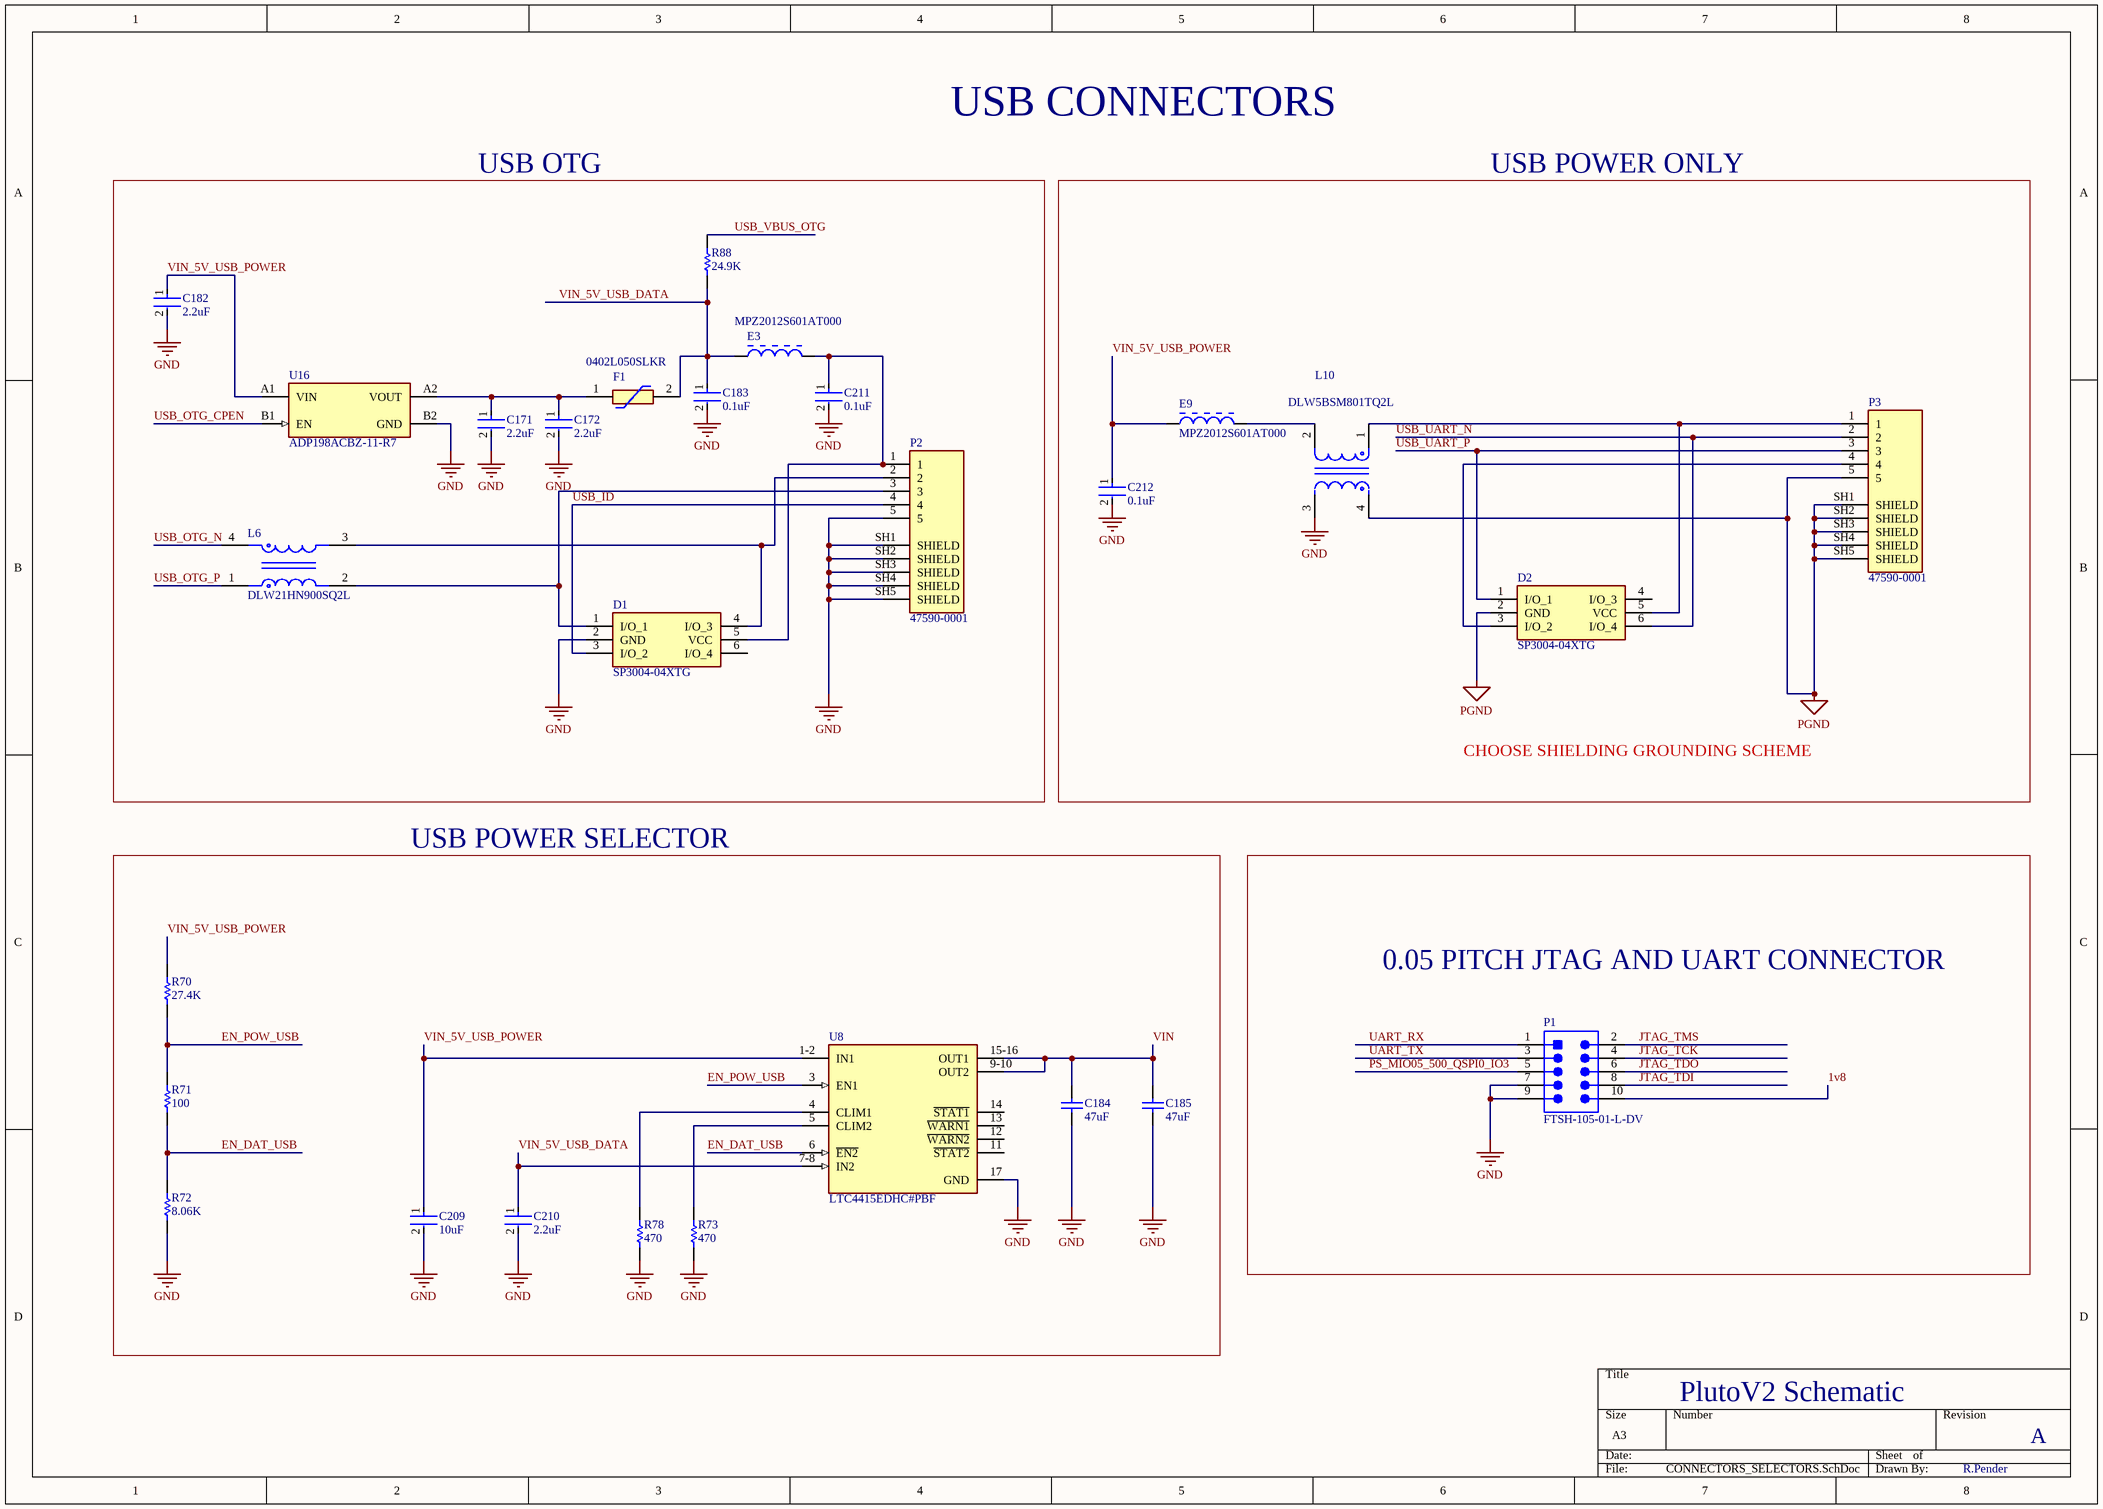
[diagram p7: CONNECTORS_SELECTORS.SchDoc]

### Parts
C171  2.2uF  [FP-GRM188-0_2-IPC_C]
C172  2.2uF  [FP-GRM188-0_2-IPC_C]
C182  2.2uF  [FP-GRM188-0_2-MFG]
C183  0.1uF  [FP-CL10-IPC_A]
C184  47uF  [TAYO-JMK212BBJ476MG-T_L]
C185  47uF  [TAYO-JMK212BBJ476MG-T_L]
C209  10uF  [FP-GRM188-0_15-MFG]
C210  2.2uF  [FP-GRM188-0_2-IPC_C]
C211  0.1uF  [FP-CL10-IPC_A]
C212  0.1uF  [FP-CL10-IPC_A]
D1  SP3004-04XTG  [SOTFL50P160X60-6N]
D2  SP3004-04XTG  [SOTFL50P160X60-6N]
E3  MPZ2012S601AT000  [TDK-MPZ2012_V]
E9  MPZ2012S601AT000  [TDK-MPZ2012_V]
F1  0402L050SLKR  [0402L010SLKR]
L6  DLW21HN900SQ2L  [FP-DLW21HN-MFG]
L10  DLW5BSM801TQ2L  [FP-DLW5BS-MFG]
P1  FTSH-105-01-L-DV  [SMTC-FTSH-105-01-L-DV_V]
P2  47590-0001  [MOLEX_47590-0001]
P3  47590-0001  [MOLEX_47590-0001]
R70  27.4K  [2-0402]
R71  100  [2-0402]
R72  8.06K  [2-0402]
R73  470  [RESC1005X40X25ML05T10]
R78  470  [RESC1005X40X25ML05T10]
R88  24.9K  [2-0402]
U8  LTC4415EDHC#PBF  [FP-DHC-16-05-08-1872-MFG]
U16  ADP198ACBZ-11-R7  [FP-CB-4-4-MFG]

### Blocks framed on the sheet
USB OTG: C171 C172 C182 C183 C211 D1 E3 F1 L6 P2 R88 U16
USB POWER ONLY: C212 D2 E9 L10 P3
USB POWER SELECTOR: C184 C185 C209 C210 R70-R73 R78 U8
0.05 PITCH JTAG AND UART CONNECTOR: P1

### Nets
GND: C171.2 C172.2 C182.2 C183.2 C184.2 C185.2 C209.2 C210.2 C211.2 C212.2 D1.2(GND) L10.3 P1.7 P1.9 P2.5 P2.SH1(SHIELD) P2.SH2(SHIELD) P2.SH3(SHIELD) P2.SH4(SHIELD) P2.SH5(SHIELD) R72.2 R73.2 R78.2 U8.17(GND) U16.B2(GND)
PGND: D2.2(GND) L10.4 P3.5 P3.SH1(SHIELD) P3.SH2(SHIELD) P3.SH3(SHIELD) P3.SH4(SHIELD) P3.SH5(SHIELD)
1v8: P1.10
EN_DAT_USB: R71.2 R72.1 U8.6(~{EN2})
EN_POW_USB: R70.2 R71.1 U8.3(EN1)
JTAG_TCK: P1.4
JTAG_TDI: P1.8
JTAG_TDO: P1.6
JTAG_TMS: P1.2
PS_MIO05_500_QSPI0_IO3: P1.5
UART_RX: P1.1
UART_TX: P1.3
USB_ID: D1.3(I/O_2) P2.4
USB_OTG_CPEN: U16.B1(EN)
USB_OTG_N: L6.4
USB_OTG_P: L6.1
USB_UART_N: D2.6(I/O_4) P3.2
USB_UART_P: D2.1(I/O_1) P3.3
USB_VBUS_OTG: R88.2
VIN: C184.1 C185.1 U8.9-10(OUT2) U8.15-16(OUT1)
VIN_5V_USB_DATA: C183.1 C210.1 E3.1 F1.2 R88.1 U8.7-8(IN2)
VIN_5V_USB_POWER: C182.1 C209.1 C212.1 E9.1 R70.1 U8.1-2(IN1) U16.A1(VIN)
NetC171_1: C171.1 C172.1 F1.1 U16.A2(VOUT)
NetC211_1: C211.1 D1.5(VCC) E3.2 P2.1
NetD1_1: D1.1(I/O_1) L6.2 P2.3
NetD1_4: D1.4(I/O_3) L6.3 P2.2
NetD2_3: D2.3(I/O_2) P3.4
NetD2_5: D2.5(VCC) L10.1 P3.1
NetE9_2: E9.2 L10.2
NetR73_1: R73.1 U8.5(CLIM2)
NetR78_1: R78.1 U8.4(CLIM1)

Not connected (* = marked no-connect by the designer): D1 6(I/O_4); D2 4(I/O_3); U8 11(~{STAT2}) 12(~{WARN2}) 13(~{WARN1}) 14(~{STAT1})

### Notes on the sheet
- USB CONNECTORS
- CHOOSE SHIELDING GROUNDING SCHEME
- PlutoV2 Schematic
- A
- R.Pender

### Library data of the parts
C171 C172 C182 C210 = CMP-06035-023692-1: Chip Multilayer Ceramic Capacitors for General Purpose, 0603, 2.2uF, X5R, 15%, 10%, 50V
C183 C211 C212 = CMP-13271-004036-1: Cap Ceramic 100nF 100V X7R ±10% Pad SMD 0603 +125°C T/R
C184 C185 = CMP-2000-06498-1: as C65 on sheet ZYNQ JTAG and Decoupling
C209 = CMP-06035-003612-1: Chip Multilayer Ceramic Capacitors for General Purpose, 0603, 10uF, X5R, 15%, 20%, 10V
D1 D2 = SP3004-04XTG: TVS Diode (Uni-directional); Manufacturer_Name: LITTELFUSE
E3 E9 = CMP-2000-05401-1: Chip Bead, 0.1 Ohm, 2 A, -55 to 125 degC, 2-Pin SMD (0805), RoHS, Tape and Reel; PCN Part Number: MMZ,MPSSeriesOct/2014; Manufacturer: TDK; Impedance @ Frequency: 600Ohm@100MHz; Other Names: 445-2206-6; Catalog Drawings: (MMZ,MPZ)2012SeriesTop / (MMZ,MPZ)2012SeriesFootprint / (MMZ,MPZ)2012SeriesSide; DC Resistance (DCR): 100mOhmMax; Current Rating: 2A; Product Training Modules: EMCComponents; Filter Type: DifferentialMode-Single; Online Catalog: MPZ2012Series
F1 = 0402L050SLKR: Resettable Fuse; Manufacturer_Name: LITTELFUSE
L6 = CMP-06045-000050-1: CMC 330MA 2LN 90 OHM SMD; Tolerance: 25%; Frequency: 100MHz; Shielding: Unshielded; Impedance: 90R; Number of Lines: 2; DC Resistance (DCR): 350mR; Voltage Rating: 50V
L10 = CMP-06045-000287-1: Common Mode Choke, 2020, 800Ω @ 100MHz, 0.056Ω, 40%, 2A; Number of Lines: 2; Impedance: 800R; DC Resistance (DCR): 56mR; Voltage Rating (DC): 50V
P1 = CMP-2000-05354-1: Male Header, Pitch 1.27 mm, 2 x 5 Position, Height 5.96 mm, -55 to 125 degC, RoHS, Bulk; Manufacturer: Samtec; Connector Type: Header,Unshrouded; Pitch: 0.050"(1.27mm); Mating Products: FLE-105-01-G-DV-TR-ND-CONNSKT1.27MM10POSDUALSMDCLP-105-02-G-D-P-TR-ND-CONNRCPT10POSDUAL.05"SMDSFMC-105-L2-S-D-TR-ND-CONN.05"SURFACE10POSSMTSFMH-105-02-L-D-TR-ND-CONNRECEPT10POS.50"SMTFLE-105-01-G-DV-A-ND-CONNSKT1.27MM10POSDUALSMDCLP-105-02-G-D-BE-ND-CONNRCPT10POSDUAL.05"SMDFLE-105-01-G-DV-A-P-ND-CONNSKT1.27MM10POSDUALSMDSAM1153-05-ND-CONNRCPT10POSDUAL.05"SMDSAM1155-05-ND-CONNRCPT10POSDUAL.05"SMDSAM1154-05-ND-CONNRCPT10POSDUAL.05"SMDSFMH-105-02-L-D-LC-ND-CONNRECEPT10POS.50"SMTSAM1226-05-ND-CONNRCPT.05"10POSDUALSMD; Catalog Drawings: FTSHSeriesFTSHSeriesSMTSide; Other Names: SAM1161-05; EDA / CAD Models: DownloadfromAcceleratedDesigns; Number of Positions Loaded: All; Number of Positions: 10; Featured Product: Board-To-BoardInterconnectSystems; Online Catalog: FTSHSeries; Product Training Modules: Board-to-BoardConnectors
P2 P3 = 47590-0001: USB - micro AB Receptacle Connector 5 Position Surface Mount, Right Angle; Through Hole; MF: Molex
R70-R72 R88 = ERJ2RK: as R13 on sheet USB
R73 R78 = CMP-2002-07697-1: Part Number: RC0402FR-07470RL; Manufacturer: Yageo / Phycomp
U8 = CMP-0479-00072-2: IC OR CTRLR SRC SELECT 16DFN; Max Output Current: 4A; Operating Supply Current: 44uA
U16 = CMP-09134-000005-1: IC PWR SWITCH P-CHAN 1:1 4WLCSP; Output Configuration: High Side; On-State Resistance: 40mR; Max Input Voltage: 6.5V; Fault Protection: Reverse Current; Min Input Voltage: 1.65V; Output Current per Channel: 1A; Interface: On/Off; Number of Outputs: 1; Operating Supply Current: 1.1uA

## Sheet POWERREG.SchDoc
size A3; SheetNumber: 9; SheetTotal: 13; SPICEModelCacheORBVXWHQ: <root> / <DocumentId>ORBVXWHQ</DocumentId> / <CacheFrame Number="0"> / <Model Name="emk105bj105_v-f" Kind="CKT"> / <Text>* EMK105BJ105_V-F     SPICE MODEL  ( General Type ) / *-------------------------------------------------------------------------------------------------------- / * Model Generated by TAIYO YUDEN Corporation (http://www.ty-top.com) / * Version 1.0 / * TAIYO YUDEN Control No. 170508_130520 / * Copyright(c) 2012 TAIYO YUDEN CO.,LTD. All Rights Reserved. / *-------------------------------------------------------------------------------------------------------- / * / * Products Name : Multilayer Ceramic Capacitors / * / * Characteristics : / *     Capacitance : 1 uF , Rated Voltage : 16V , TCC : X5R / *     Case Size : 1.0 x 0.5 / 0.039 x 0.02 [mm/inch] , Thickness : 0.5 / 0.02 [mm/inch] / *     (Conditions: Temperature = 25 degC , DC Bias Current/Voltage = 0A / 0V) / * / * Frequency Range : 40Hz - 3GHz / * / * External Node Assignments : / * / *  1  o---¦ ¦---o  2 / * / *-------------------------------------------------------------------------------------------------------- / .SubCkt EMK105BJ105_V-F 1 2 / **************************** / C0 1 110 0.68309u / Cm 1 101 0.26053u / C1 101 102 0.94076u / Rc1 101 102 1.9029k / C2 102 103 0.66707u / Rc2 102 103 120.36 / C3 103 110 0.57203u / Rc3 103 110 2.1097 / C2m 1 301 0.1871u / C21 301 302 3.2494u / Rc21 301 302 1.1117k / C22 302 303 2.1014u / Rc22 302 303 1.484k / C23 303 304 2.1172u / Rc23 303 304 1.3876k / C24 304 305 0.75729u / Rc24 304 305 332.59 / C25 305 306 0.94401u / Rc25 305 306 249.09 / C26 306 307 0.34674u / Rc26 306 307 28.352 / C27 307 308 0.37158u / Rc27 307 308 19.989 / C28 308 309 0.17933u / Rc28 308 309 31.748 / C29 309 110 0.016445u / Rc29 309 110 1.0592 / Rp0 1 110 100Meg / L0 110 120 0.2216n / Lm 120 130 0.1509n / L1 120 121 0.12659n / RL1 121 130 0.85161 / L2 120 122 0.15996n / RL2 122 130 0.42469 / L3 120 123 7.9543n / RL3 123 130 0.54643m / CR 120 124 0.24334u / LR 124 125 0.090738n / RR 125 130 68.076m / CL 130 140 2.7354p / LL 130 140 0.10762n / RL 130 140 50.614 / Rs 140 2 7.5416m / **************************** / .ends EMK105BJ105_V-F</Text> / </Model> / </CacheFrame> / </root>
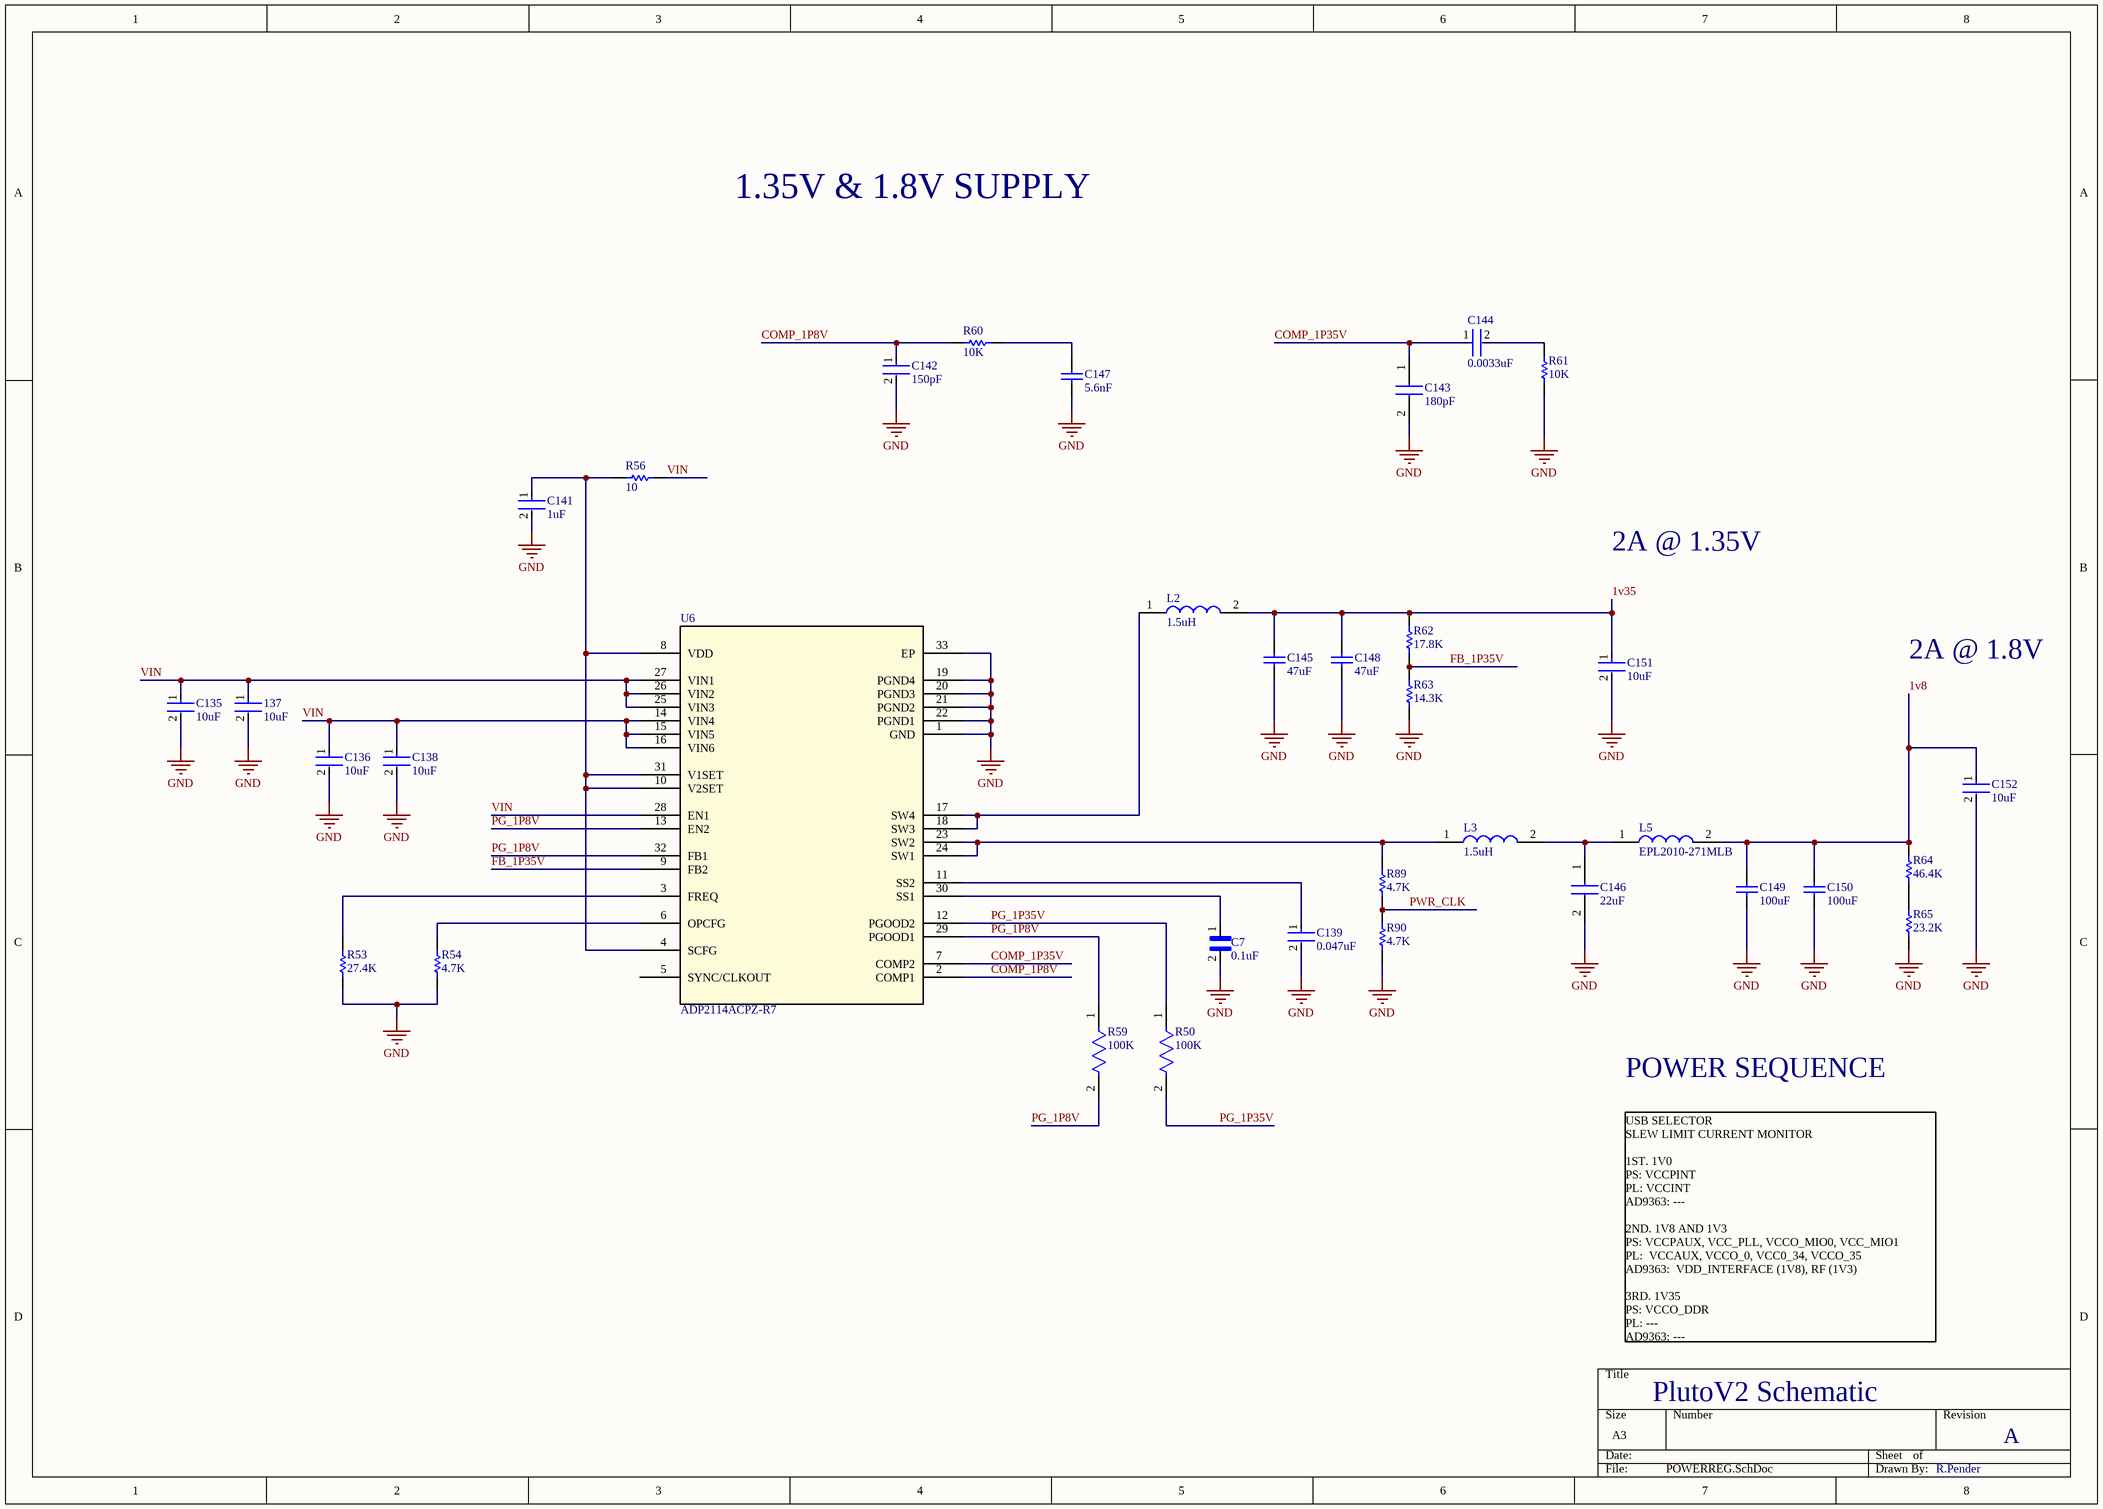
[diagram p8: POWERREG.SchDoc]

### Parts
137  10uF  [FP-GRM188-0_15-MFG]
C7  0.1uF  [CAPC0603X33N]
C135  10uF  [FP-GRM188-0_15-MFG]
C136  10uF  [FP-GRM188-0_15-MFG]
C138  10uF  [FP-GRM188-0_15-MFG]
C139  0.047uF  [FP-GCM155-0_05-IPC_C]
C141  1uF  [FP-0402-L_1_0_0_05-W_0_5-IPC_A]
C142  150pF  [FP-GCM155-0_05-IPC_C]
C143  180pF  [CAPC1005X55N]
C144  0.0033uF  [FP-CC0402-MFG]
C145  47uF  [TAYO-JMK212BBJ476MG-T_L]
C146  22uF  [CAPC2012X95N]
C147  5.6nF  [CAPC1005X56X25NL10T15]
C148  47uF  [TAYO-JMK212BBJ476MG-T_L]
C149  100uF  [CAPC3216X190X55ML30T25]
C150  100uF  [CAPC3216X190X55ML30T25]
C151  10uF  [FP-GRM188-0_1-e0_2_0_55-IPC_A]
C152  10uF  [FP-GRM188-0_1-e0_2_0_55-IPC_A]
L2  1.5uH  [XFL4020152MEB]
L3  1.5uH  [XFL4020152MEB]
L5  EPL2010-271MLB  [EPL2010271MLB]
R50  100K  [FP-ERJ2RK-IPC_C]
R53  27.4K  [2-0402]
R54  4.7K  [2-0402]
R56  10  [RESC0603X26X15LL03T05]
R59  100K  [FP-ERJ2RK-IPC_C]
R60  10K  [2-0402]
R61  10K  [2-0402]
R62  17.8K  [3-0603]
R63  14.3K  [3-0603]
R64  46.4K  [2-0402]
R65  23.2K  [2-0402]
R89  4.7K  [2-0402]
R90  4.7K  [2-0402]
U6  ADP2114ACPZ-R7  [CP_32_2_ADI]

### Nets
GND: 137.2 C7.2 C135.2 C136.2 C138.2 C139.2 C141.2 C142.2 C143.2 C145.2 C146.2 C147.2 C148.2 C149.2 C150.2 C151.2 C152.2 R53.2 R54.2 R61.2 R63.2 R65.2 R90.2 U6.1(GND) U6.19(PGND4) U6.20(PGND3) U6.21(PGND2) U6.22(PGND1) U6.33(EP)
1v8: C149.1 C150.1 C152.1 L5.2 R64.1
1v35: C145.1 C148.1 C151.1 L2.2 R62.1
COMP_1P8V: C142.1 R60.1 U6.2(COMP1)
COMP_1P35V: C143.1 C144.1 U6.7(COMP2)
FB_1P35V: R62.2 R63.1 U6.9(FB2)
PG_1P8V: R59.1 R59.2 U6.13(EN2) U6.29(PGOOD1) U6.32(FB1)
PG_1P35V: R50.1 R50.2 U6.12(PGOOD2)
PWR_CLK: R89.2 R90.1
VIN: 137.1 C135.1 C136.1 C138.1 R56.2 U6.14(VIN4) U6.15(VIN5) U6.16(VIN6) U6.25(VIN3) U6.26(VIN2) U6.27(VIN1) U6.28(EN1)
NetC7_1: C7.1 U6.30(SS1)
NetC139_1: C139.1 U6.11(SS2)
NetC141_1: C141.1 R56.1 U6.4(SCFG) U6.8(VDD) U6.10(V2SET) U6.31(V1SET)
NetC144_2: C144.2 R61.1
NetC146_1: C146.1 L3.2 L5.1
NetC147_1: C147.1 R60.2
NetL2_1: L2.1 U6.17(SW4) U6.18(SW3)
NetL3_1: L3.1 R89.1 U6.23(SW2) U6.24(SW1)
NetR53_1: R53.1 U6.3(FREQ)
NetR54_1: R54.1 U6.6(OPCFG)
NetR64_2: R64.2 R65.1

Not connected (* = marked no-connect by the designer): U6 5(SYNC/CLKOUT)

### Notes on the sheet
- 1.35V & 1.8V SUPPLY
- 2A @ 1.35V
- 2A @ 1.8V
- POWER SEQUENCE
- USB SELECTOR                                                                                                    SLEW LIMIT CURRENT MONITOR
  1ST. 1V0
  PS: VCCPINT
  PL: VCCINT
  AD9363: ---
  2ND. 1V8 AND 1V3
  PS: VCCPAUX, VCC_PLL, VCCO_MIO0, VCC_MIO1
  PL:  VCCAUX, VCCO_0, VCC0_34, VCCO_35
  AD9363:  VDD_INTERFACE (1V8), RF (1V3)
  3RD. 1V35
  PS: VCCO_DDR
  PL: ---
  AD9363: ---
- PlutoV2 Schematic
- A
- R.Pender

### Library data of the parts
137 C135 C136 C138 = CMP-06035-003612-1: as C209 on sheet CONNECTORS_SELECTORS
C7 = GRM033R61C104ME84D: as C46 on sheet USB
C139 = CMP-2008-03720-2: Ceramic Capacitor for Automotive 47nF ±10% 25VDC X7R 0402 Paper T/R; Voltage Rating: 25V
C141 = CMP-14477-000104-2: as C126 on sheet AD9363
C142 = CMP-06035-010111-1: Ceramic Capacitor for Automotive 150pF ±1% 50VDC C0G 0402 Paper T/R
C143 = CGJ2B2C0G1H181J050BA: Capacitor; Manufacturer_Name: TDK
C144 = CMP-1034-01779-2: CAP CER 3300PF 50V X7R 0402; Manufacturer: YAGEO; Manufacturer Part Number: CC0402KRX7R9BB332; Temperature Coefficient: 30ppm/°C; Material: Ceramic; Value: 3.3 nF; Tolerance: 0.1; Automotive Grade: NA
C145 C148 = CMP-2000-06498-1: as C65 on sheet ZYNQ JTAG and Decoupling
C146 = CL21A226KPCLRNC: Capacitor; Manufacturer_Name: Samsung Electro-Mechanics
C147 = CMP-2008-02976-1: Manufacturer: AVX Interconnect / Elco; Part Number: 04025C562JAT2A
C149 C150 = CMP-1662-00011-2: as C100 on sheet DDR3
C151 C152 = CMP-2006-02792-2: as C79 on sheet DDR3
L2 L3 = XFL4020-152MEB: Inductor; Manufacturer_Name: COILCRAFT
L5 = EPL2010-271MLB: Inductor; Manufacturer_Name: COILCRAFT
R50 R59 = CMP-2002-00608-4: RES SMD 100K OHM 1% 1/10W 0402; Resistance: 100kR; Voltage Rating (DC): 50V; Power Rating: 100mW; Temperature Coefficient: 100ppm/°C
R53 R54 R60 R61 R64 R65 R89 R90 = ERJ2RK: as R13 on sheet USB
R56 = CMP-2004-03448-1: Manufacturer: Panasonic; Part Number: ERJ1GNF10R0C
R62 R63 = ERJ3EK: Precision Thick Film Chip Resistor, 10 Ohm to 1M Ohm Range, 1% and 0.5% Tolerance, 0603 Size, 0.063 W
U6 = ADP2114ACPZ-R7: No Description Available; Mfr_Name: Analog Devices Inc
